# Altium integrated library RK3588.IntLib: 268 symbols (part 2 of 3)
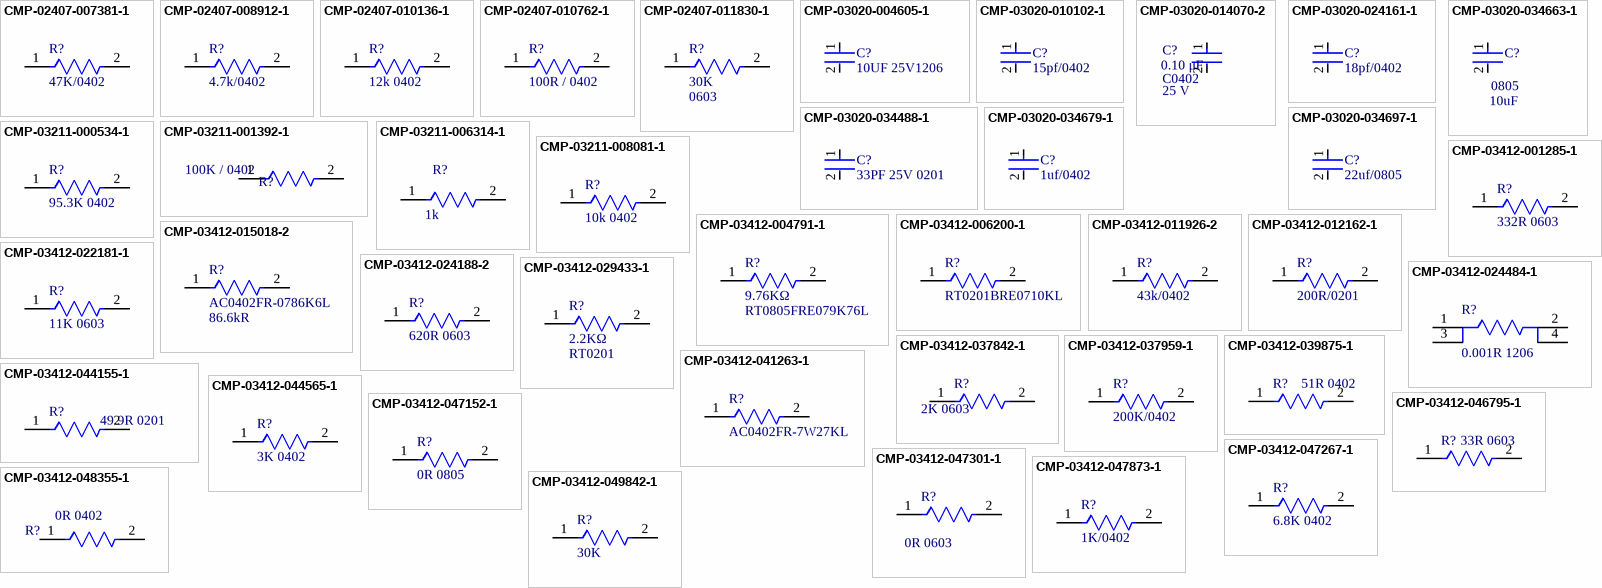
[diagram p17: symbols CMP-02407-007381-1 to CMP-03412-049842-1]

## CMP-02407-008912-1
designator R?, comment 4.7k/0402
RES SMD 1.2K OHM 1% 1/10W 0402
footprint FP-MCS0402-IPC_A
footprint FP-MCS0402-MFG
footprint FP-MCS0402-IPC_C
footprint FP-MCS0402-IPC_B
pins: 1, 2

## CMP-02407-010136-1
designator R?, comment 12k 0402
RES Thick Film, 12kΩ, 1%, 0.063W, 100ppm/°C, 0402; Max Power Dissipation: 63mW; Resistance: 12kR; MP: CRCW040212K0FKEE
footprint FP-CRCW0402-e3-MFG
footprint FP-CRCW0402-e3-IPC_A
footprint FP-CRCW0402-e3-IPC_B
footprint FP-CRCW0402-e3-IPC_C
pins: 1, 2

## CMP-02407-010762-1
designator R?, comment 100R / 0402
RES SMD 1.2K OHM 1% 1/10W 0402; Voltage Rating: 50V; Max Power Dissipation: 100mW; Temperature Coefficient: 50ppm/°C
footprint FP-MCS0402-IPC_C
footprint FP-MCS0402-MFG
footprint FP-MCS0402-IPC_B
footprint FP-MCS0402-IPC_A
pins: 1, 2

## CMP-02407-011830-1
designator R?  value 30K  Case: 0603
30K 0603 / MCT0603MC3002FP500
footprint FP-MCT0603-MFG
footprint FP-MCT0603-IPC_B
footprint FP-MCT0603-IPC_A
footprint FP-MCT0603-IPC_C
pins: 1, 2

## CMP-03020-004605-1
designator C?, comment 10UF 25V1206
CAP CER 10UF 25V X7R 1206 / C1206C106K3RACAUTO; Manufacturer: KEMET; Material: Ceramic; Automotive Grade: Grade 1; Temperature Coefficient: 15%; Tolerance: 10%
footprint FP-C1206C-EH-MFG
footprint FP-C1206C-EH-IPC_C
footprint FP-C1206C-EH-IPC_B
footprint FP-C1206C-EH-IPC_A
pins: 1, 2

## CMP-03020-010102-1
designator C?, comment 15pf/0402
C0402 15 pF X8R 10.00% 50 V; Manufacturer Part Number: C0402C150K5HACAUTO; Manufacturer: Kemet; Tolerance: 0.1; Material: Ceramic; Temperature Coefficient: 15%; Capacitance: 15 pF; Voltage Rating: 50 V; Value: 15 pF
footprint FP-C0402-BB-MFG
footprint FP-C0402-BB-IPC_C
footprint FP-C0402-BB-IPC_B
footprint FP-C0402-BB-IPC_A
pins: 1, 2

## CMP-03020-014070-2
designator C?, comment value 0.10 μF  Package: C0402  Voltage Rating: 25 V  (hidden comment: C0402C104M3PAC7867)
CAP CER 0.1UF 25V X5R 0402; Manufacturer: Kemet; Material: Ceramic; Tolerance: 0.2; Temperature Coefficient: 15%
footprint FP-C0402-BB-MFG
footprint FP-C0402-BB-IPC_C
footprint FP-C0402-BB-IPC_B
footprint FP-C0402-BB-IPC_A
pins: 1, 2

## CMP-03020-024161-1
designator C?, comment 18pf/0402
C0402 18 pF X8R 5.00% 50 V; Manufacturer: Kemet; Manufacturer Part Number: 0402CG180J500NT; Value: 18 pF; Material: Ceramic; Temperature Coefficient: 15%; Tolerance: 0.05; Voltage Rating: 50 V
footprint FP-C0402-BB-MFG
footprint FP-C0402-BB-IPC_C
footprint FP-C0402-BB-IPC_B
footprint FP-C0402-BB-IPC_A
pins: 1, 2

## CMP-03020-034488-1
designator C?, comment 33PF 25V 0201
CAP CER 33PF 25V NP0 0201; Manufacturer Part Number: C0201C330K3GACTU; Manufacturer: KEMET; Standoff Height: 0mm; Tolerance: 0.1; Temperature Characteristic: C0G; Temperature Coefficient: 30ppm/°C; Material: Ceramic
footprint FP-C0201-AB-MFG
footprint FP-C0201-AB-IPC_C
footprint FP-C0201-AB-IPC_B
footprint FP-C0201-AB-IPC_A
pins: 1, 2

## CMP-03020-034663-1
designator C?, comment Capacitance: 10uF  Case/Package: 0805  (hidden comment: C0805C106K3PACTU)
CAP CER 10UF 25V X5R 0805; Dissipation Factor: 10%; Dielectric Material: Ceramic
footprint FP-C0805C106K3PACTU-MFG
footprint FP-C0805C106K3PACTU-IPC_C
footprint FP-C0805C106K3PACTU-IPC_B
footprint FP-C0805C106K3PACTU-IPC_A
pins: 1, 2

## CMP-03020-034679-1
designator C?, comment 1uf/0402
CAP CER 1UF 16V X5R 0402; Dielectric Material: Ceramic; Tolerance: 10%
footprint FP-C0402C-BB-IPC_B
footprint FP-C0402C-BB-MFG
footprint FP-C0402C-BB-IPC_A
footprint FP-C0402C-BB-IPC_C
pins: 1, 2

## CMP-03020-034697-1
designator C?, comment 22uf/0805
CAP CER 22UF 10V X5R 0805; Tolerance: 20%; Dissipation Factor: 10%; Dielectric Material: Ceramic
footprint FP-C0805C226M8PACTU-MFG
footprint FP-C0805C226M8PACTU-IPC_C
footprint FP-C0805C226M8PACTU-IPC_B
footprint FP-C0805C226M8PACTU-IPC_A
pins: 1, 2

## CMP-03211-000534-1
designator R?, comment 95.3K 0402
RP73P 0402 95.3KΩ 0.1W 25ppm/°C 0.10% 50V; Manufacturer Part Number: RP73PF1E95K3BTDF; Manufacturer: TE Connectivity
footprint FP-RP73P-1E-MFG
footprint FP-RP73P-1E-IPC_C
footprint FP-RP73P-1E-IPC_B
footprint FP-RP73P-1E-IPC_A
pins: 1, 2

## CMP-03211-001392-1
designator R?, comment 100K / 0402
SMD Precision Pulse Thick Film Chip Resistor; Manufacturer Part Number: CRGP0402F100K; Manufacturer: TE; Value: 100KΩ; Power Rating: 0.125W; Tolerance: 0.01; Temperature Coefficient: ±100ppm/°C; Voltage Rating: 50V
footprint FP-CRGP0402-IPC_C
footprint FP-CRGP0402-IPC_B
footprint FP-CRGP0402-IPC_A
pins: 1, 2

## CMP-03211-006314-1
designator R?, comment 1k
CRGCQ0402 1KΩ 1% ±100ppm/°C 50V; Manufacturer Part Number: CRGCQ0402F1K0; Manufacturer: TE Connectivity; Power Rating: 0.0625W; Tolerance: 0.01
footprint FP-CRGCQ0402-IPC_C
footprint FP-CRGCQ0402-IPC_B
footprint FP-CRGCQ0402-IPC_A
pins: 1, 2

## CMP-03211-008081-1
designator R?, comment 10k 0402
CRGCQ 0402 10K 5%; Manufacturer: TE Connectivity; Manufacturer Part Number: CRGCQ0402J10K; Power Rating: 0.0625W; Tolerance: 0.05; Voltage Rating: 50V; Temperature Coefficient: ±100ppm/°C; Resistance: 10KΩ; Value: 10KΩ
footprint FP-CRGCQ0402-IPC_C
footprint FP-CRGCQ0402-IPC_B
footprint FP-CRGCQ0402-IPC_A
pins: 1, 2

## CMP-03412-001285-1
designator R?, comment 332R 0603
RES SMD 332 OHM 0.1% 1/10W 0603; Manufacturer Part Number: RT0603BRE07332RL; Manufacturer: Yageo; Voltage Rating: 75V; Tolerance: 0.001; Temperature Coefficient: 50 ppm/°C; Power Rating: 0.1W; Value: 332Ω
footprint FP-RT0603-MFG
footprint FP-RT0603-IPC_C
footprint FP-RT0603-IPC_B
footprint FP-RT0603-IPC_A
pins: 1, 2

## CMP-03412-004791-1
designator R?, comment RT0805FRE079K76L  value 9.76KΩ
RES SMD 9.76K OHM 1% 1/8W 0805; Manufacturer: Yageo; Power Rating: 0.125W; Temperature Coefficient: 50 ppm/°C; Tolerance: 0.0001; Voltage Rating: 150V
footprint FP-RT0805-MFG
footprint FP-RT0805-IPC_C
footprint FP-RT0805-IPC_B
footprint FP-RT0805-IPC_A
pins: 1, 2

## CMP-03412-006200-1
designator R?, comment RT0201BRE0710KL
RT0201 10KΩ 0.05W 50 ppm/°C 0.10%; Manufacturer: Yageo; Voltage Rating: 25V; Tolerance: 0.001
footprint FP-RT0201-MFG
footprint FP-RT0201-IPC_C
footprint FP-RT0201-IPC_B
footprint FP-RT0201-IPC_A
pins: 1, 2

## CMP-03412-011926-2
designator R?, comment 43k/0402
RES 43kΩ ±1% 0.063W 0402; Power Rating: 63mW; Temperature Coefficient: 100ppm/°C; Resistance: 43kR
footprint FP-AC0402-MFG
footprint FP-AC0402-IPC_C
footprint FP-AC0402-IPC_B
footprint FP-AC0402-IPC_A
pins: 1, 2

## CMP-03412-012162-1
designator R?, comment 200R/0201
RES SMD 200 OHM 0.5% 1/20W 0201; Manufacturer Part Number: RT0201DRD07200RL; Manufacturer: Yageo; Tolerance: 0.005; Value: 200Ω; Power Rating: 0.05W; Voltage Rating: 25V; Temperature Coefficient: 25 ppm/°C
footprint FP-RT0201-MFG
footprint FP-RT0201-IPC_C
footprint FP-RT0201-IPC_B
footprint FP-RT0201-IPC_A
pins: 1, 2

## CMP-03412-015018-2
designator R?, comment AC0402FR-0786K6L  Resistance: 86.6kR
RES 86.6kΩ ±1% 0.063W 0402; Voltage Rating: 50V; Power Rating: 62.5mW; Max Power Dissipation: 63mW; Temperature Coefficient: 100ppm/°C
footprint FP-AC0402-IPC_B
footprint FP-AC0402-IPC_C
footprint FP-AC0402-IPC_A
footprint FP-AC0402-MFG
pins: 1, 2

## CMP-03412-022181-1
designator R?, comment 11K 0603
RES SMD 11K OHM 0.1% 1/10W 0603; Manufacturer Part Number: RT0603BRC0711KL; Manufacturer: Yageo; Temperature Coefficient: 15 ppm/°C; Tolerance: 0.001; Value: 11KΩ; Voltage Rating: 75V; Power Rating: 0.1W
footprint FP-RT0603-MFG
footprint FP-RT0603-IPC_C
footprint FP-RT0603-IPC_B
footprint FP-RT0603-IPC_A
pins: 1, 2

## CMP-03412-024188-2
designator R?, comment 620R 0603
RES 620Ω 1.00% 0.1W 0603; Max Power Dissipation: 100mW; Working Voltage: 75V; Voltage Rating: 50V; Tolerance: 1%; Temperature Coefficient: 100ppm/°C
footprint FP-AC0603-IPC_C
footprint FP-AC0603-IPC_A
footprint FP-AC0603-MFG
footprint FP-AC0603-IPC_B
pins: 1, 2

## CMP-03412-024484-1
designator R?, comment 0.001R 1206
METAL CURRECT SENSOR 4 TERMINATI; Manufacturer Part Number: PS0612FKF070R001L; Manufacturer: Yageo; Value: 1mΩ; Temperature Coefficient: 100ppm/°C; Power Rating: 1W; Tolerance: 1%
footprint FP-PS0612-MFG
pins: 1, 2, 3, 4

## CMP-03412-029433-1
designator R?, comment Resistance: 2.2KΩ  Package: RT0201  (hidden comment: RT0201FRE072K2L)
RES SMD 2.2K OHM 1% 1/20W 0201; Manufacturer: Yageo; Value: 2.2KΩ; Power Rating: 0.05W; Temperature Coefficient: 50 ppm/°C; Tolerance: 0.01; Voltage Rating: 25V
footprint FP-RT0201-MFG
footprint FP-RT0201-IPC_C
footprint FP-RT0201-IPC_B
footprint FP-RT0201-IPC_A
pins: 1, 2

## CMP-03412-037842-1
designator R?, comment 2K 0603
RES 2kΩ 1.00% 0.1W 0603; Resistance: 2kR; Tolerance: 1%
footprint FP-AC0603-IPC_B
footprint FP-AC0603-IPC_C
footprint FP-AC0603-MFG
footprint FP-AC0603-IPC_A
pins: 1, 2

## CMP-03412-037959-1
designator R?, comment 200K/0402
RES 200kΩ ±5% 0.063W 0402; Power Rating: 62.5mW; Max Power Dissipation: 63mW; Resistance: 200kR; Temperature Coefficient: 100ppm/°C; Voltage Rating: 50V
footprint FP-AC0402-IPC_B
footprint FP-AC0402-IPC_A
footprint FP-AC0402-IPC_C
footprint FP-AC0402-MFG
pins: 1, 2

## CMP-03412-039875-1
designator R?, comment 51R 0402
Anti-Sulfurated Chip Resistors Automotive Grade 51Ω 5% 100ppm/°C 0402; Max Power Dissipation: 63mW
footprint FP-AF0402-IPC_C
footprint FP-AF0402-IPC_B
footprint FP-AF0402-MFG
footprint FP-AF0402-IPC_A
pins: 1, 2

## CMP-03412-041263-1
designator R?, comment AC0402FR-7W27KL
RES 27kΩ ±1% 0.125W 0402
footprint FP-AC0402-IPC_B
footprint FP-AC0402-IPC_C
footprint FP-AC0402-MFG
footprint FP-AC0402-IPC_A
pins: 1, 2

## CMP-03412-044155-1
designator R?, comment 49.9R 0201
Anti-Sulfurated Chip Resistors Automotive Grade 49.9Ω 1% 200ppm/°C 0201; Max Power Dissipation: 50mW
footprint FP-AF0201-MFG
footprint FP-AF0201-IPC_A
footprint FP-AF0201-IPC_C
footprint FP-AF0201-IPC_B
pins: 1, 2

## CMP-03412-044565-1
designator R?, comment 3K 0402
Thin Film Chip Resistors Automotive Grade 3kΩ 1% 50ppm/°C 0402; MP: AT0402FRE073KL
footprint FP-AT0402-IPC_B
footprint FP-AT0402-MFG
footprint FP-AT0402-IPC_A
footprint FP-AT0402-IPC_C
pins: 1, 2

## CMP-03412-046795-1
designator R?, comment 33R 0603
Anti-Sulfurated Chip Resistors Automotive Grade 33Ω 1% 100ppm/°C 0603; Max Power Dissipation: 100mW; MN: AF0603FR-0733RL
footprint FP-AF0603-IPC_C
footprint FP-AF0603-IPC_A
footprint FP-AF0603-MFG
footprint FP-AF0603-IPC_B
pins: 1, 2

## CMP-03412-047152-1
designator R?, comment 0R 0805
Anti-Sulfurated Chip Resistor Automotive Grade 0Ω Jumper 0.125W 0805; Max Power Dissipation: 125mW
footprint FP-AF0805-IPC_B
footprint FP-AF0805-IPC_C
footprint FP-AF0805-MFG
footprint FP-AF0805-IPC_A
pins: 1, 2

## CMP-03412-047267-1
designator R?, comment 6.8K 0402
RES 6.8kΩ ±5% 0.125W 0402; MP: AC0402JR-7W6K8L
footprint FP-AC0402-MFG
footprint FP-AC0402-IPC_B
footprint FP-AC0402-IPC_C
footprint FP-AC0402-IPC_A
pins: 1, 2

## CMP-03412-047301-1
designator R?, comment 0R 0603
RES 0Ω 5.00% 0.1W 0603; Resistance: 0mR; Tolerance: 5%
footprint FP-AC0603-IPC_C
footprint FP-AC0603-IPC_B
footprint FP-AC0603-MFG
footprint FP-AC0603-IPC_A
pins: 1, 2

## CMP-03412-047873-1
designator R?, comment 1K/0402
RES 1kΩ ±1% 0.063W 0402
footprint FP-AC0402-IPC_C
footprint FP-AC0402-IPC_A
footprint FP-AC0402-IPC_B
footprint FP-AC0402-MFG
pins: 1, 2

## CMP-03412-048355-1
designator R?, comment 0R 0402
Anti-Sulfurated Chip Resistors Automotive Grade 0Ω 0402; Tolerance: 5%; MP: AF0402JR-070RL
footprint FP-AF0402-MFG
footprint FP-AF0402-IPC_B
footprint FP-AF0402-IPC_A
footprint FP-AF0402-IPC_C
pins: 1, 2

## CMP-03412-049842-1
designator R?, comment 30K
Thin Film Chip Resistors Automotive Grade 30kΩ 1% 50ppm/°C 0603
footprint FP-AT0603-IPC_B
footprint FP-AT0603-MFG
footprint FP-AT0603-IPC_C
footprint FP-AT0603-IPC_A
pins: 1, 2

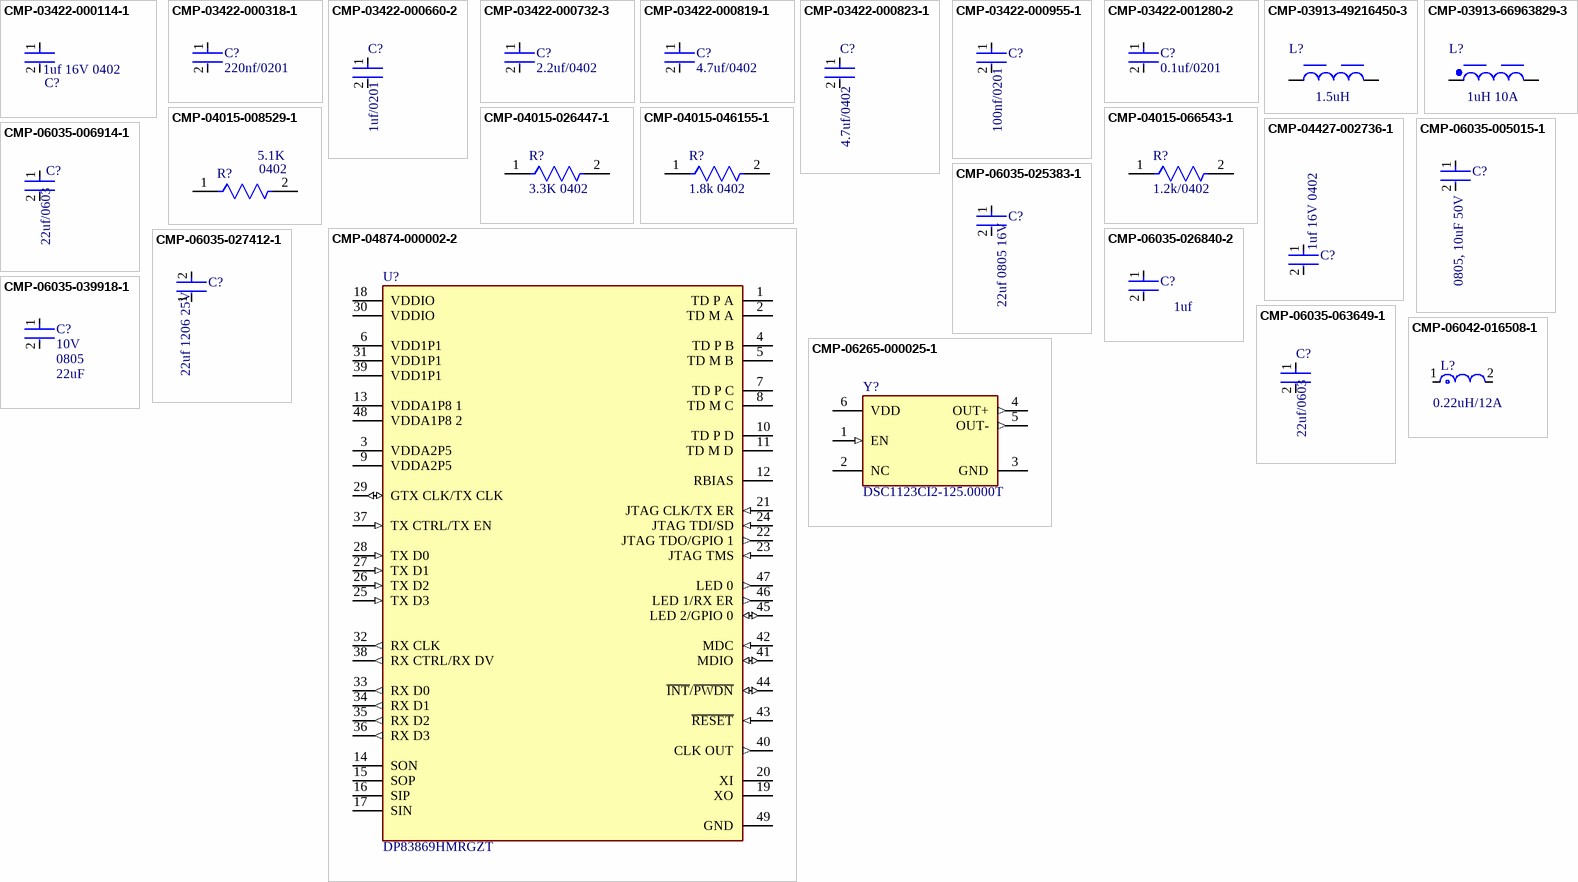
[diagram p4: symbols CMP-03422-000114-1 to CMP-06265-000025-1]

## CMP-03422-000114-1
designator C?, comment 1uf 16V 0402
CAP CER 1UF 25V X5R 0402; Manufacturer Part Number: CC0402KRX5R8BB105; Manufacturer: YAGEO; Automotive Grade: NA; Tolerance: 0.1; Material: Ceramic; Temperature Coefficient: 30ppm/°C
footprint FP-CC0402-MFG
footprint FP-CC0402-IPC_C
footprint FP-CC0402-IPC_B
footprint FP-CC0402-IPC_A
pins: 1, 2

## CMP-03422-000318-1
designator C?, comment 220nf/0201
CC0201 220 nF X5R 10.00% 10 V; Manufacturer: Yageo; Material: Ceramic; Capacitance: 220 nF; MN: CC0201KRX5R6BB224; Voltage Rating: 10 V; Temperature Coefficient: 15%; Value: 220 nF; Tolerance: 0.1
footprint FP-CC0201-BA-MFG
footprint FP-CC0201-BA-IPC_C
footprint FP-CC0201-BA-IPC_B
footprint FP-CC0201-BA-IPC_A
pins: 1, 2

## CMP-03422-000660-2
designator C?, comment 1uf/0201
1uF 6.3V X5R ±20% 0201 Multilayer Ceramic Capacitors MLCC - SMD/SMT ROHS; Manufacturer: Yageo; Manufacturer Part Number: CC0201MRX5R5BB105; Tolerance: 0.2; Temperature Coefficient: 15%; MN: CL03A105MQ3CSNH
footprint FP-CC0201-BA-MFG
footprint FP-CC0201-BA-IPC_C
footprint FP-CC0201-BA-IPC_B
footprint FP-CC0201-BA-IPC_A
signal-integrity model Model Name (Model Description)
pins: 1, 2

## CMP-03422-000732-3
designator C?, comment 2.2uf/0402
CAP CER 2.2UF 16V X5R 0402; Tolerance: 10%
footprint FP-CC0402-CC-MFG
footprint FP-CC0402-CC-IPC_C
footprint FP-CC0402-CC-IPC_B
footprint FP-CC0402-CC-IPC_A
pins: 1, 2

## CMP-03422-000819-1
designator C?, comment 4.7uf/0402
CAP CER 4.7UF 16V X5R 0402; Manufacturer Part Number: CC0402MRX5R7BB475; Manufacturer: YAGEO; Tolerance: 0.2; Automotive Grade: NA; Material: Ceramic; Temperature Coefficient: 30ppm/°C
footprint FP-CC0402-MFG
footprint FP-CC0402-IPC_C
footprint FP-CC0402-IPC_B
footprint FP-CC0402-IPC_A
pins: 1, 2

## CMP-03422-000823-1
designator C?, comment 4.7uf/0402
10V 4.7uF X5R ±10% 0402 Multilayer Ceramic Capacitors MLCC - SMD/SMT ROHS; Manufacturer Part Number: CC0402KRX5R6BB475; Manufacturer: YAGEO; Automotive Grade: NA; Temperature Coefficient: 30ppm/°C; Tolerance: 0.1
footprint FP-CC0402-MFG
footprint FP-CC0402-IPC_C
footprint FP-CC0402-IPC_B
footprint FP-CC0402-IPC_A
pins: 1, 2

## CMP-03422-000955-1
designator C?, comment 100nf/0201
CC0201 100 nF X5R 20.00% 10 V; Manufacturer: Yageo; Manufacturer Part Number: CC0201MRX5R6BB104; Tolerance: 0.2; Temperature Coefficient: 15%; Capacitance: 100 nF; Voltage Rating: 10 V; Value: 100 nF; Material: Ceramic
footprint FP-CC0201-BA-MFG
footprint FP-CC0201-BA-IPC_C
footprint FP-CC0201-BA-IPC_B
footprint FP-CC0201-BA-IPC_A
pins: 1, 2

## CMP-03422-001280-2
designator C?, comment 0.1uf/0201
CAP CER 0.1UF 25V X5R 0201
footprint FP-CC0201-BB-MFG
footprint FP-CC0201-BB-IPC_C
footprint FP-CC0201-BB-IPC_B
footprint FP-CC0201-BB-IPC_A
pins: 1, 2

## CMP-03913-49216450-3
designator L?, comment 1.5uH
Fixed Ind 1.5UH 3.7A 39 Mohm SMD; Shielding: Shielded; Saturation Current: 4.5A; Inductance Tolerance: 20%; Core Material: Composite, Ferrite, Metal; Test Frequency: 100kHz; Self Resonant Frequency: 51MHz; DC Resistance (DCR): 33mΩ; Inductance: 1.5µH
footprint WE-MAPI_3020
pins: 1, 2

## CMP-03913-66963829-3
designator L?, comment 1uH 10A
Inductor Power Shielded Wirewound 1uH 20% 100KHz Metal 10.1A 0.015Ohm DCR T/R Automotive AEC-Q200; Core Material: Composite, Metal; Current Rating: 7.2A; Self Resonant Frequency: 55MHz; Inductance: 1µH; Saturation Current: 9A; DC Resistance (DCR): 12mΩ
footprint WE-MAPI_4020
pins: 1, 2

## CMP-04015-008529-1
designator R?, comment value 5.1K  Case/Package: 0402  (hidden comment: 5.1K 0402)
5.1kΩ ±1% 0.063W, 1/16W Chip Resistor 0402 (1005 Metric) Moisture Resistant Thin Film; MN: RN73R1ETTP5101F25
footprint FP-RN73R1E-IPC_C
footprint FP-RN73R1E-MFG
footprint FP-RN73R1E-IPC_B
footprint FP-RN73R1E-IPC_A
pins: 1, 2

## CMP-04015-026447-1
designator R?, comment 3.3K 0402
3.3kΩ ±1% 0.063W, 1/16W Chip Resistor 0402 (1005 Metric) Moisture Resistant Thin Film
footprint FP-RN73R1E-IPC_B
footprint FP-RN73R1E-IPC_A
footprint FP-RN73R1E-IPC_C
footprint FP-RN73R1E-MFG
pins: 1, 2

## CMP-04015-046155-1
designator R?, comment 1.8k 0402
1.8kΩ ±0.1% 0.063W, 1/16W Chip Resistor 0402 (1005 Metric) Moisture Resistant Thin Film; MN: RN73R1ETTP1801B25
footprint FP-RN73R1E-IPC_C
footprint FP-RN73R1E-IPC_A
footprint FP-RN73R1E-IPC_B
footprint FP-RN73R1E-MFG
pins: 1, 2

## CMP-04015-066543-1
designator R?, comment 1.2k/0402
1.2kΩ ±1% 0.063W, 1/16W Chip Resistor 0402 (1005 Metric) Moisture Resistant Thin Film
footprint FP-RN73R1E-IPC_B
footprint FP-RN73R1E-MFG
footprint FP-RN73R1E-IPC_A
footprint FP-RN73R1E-IPC_C
pins: 1, 2

## CMP-04427-002736-1
designator C?, comment 1uf 16V 0402
General Purpose Ceramic Capacitor, 0402, 1uF, 20%, X5R, 15%, 16V
footprint FP-0402-L_1_0_1-W_0_5_0_1-MFG
footprint FP-0402-L_1_0_1-W_0_5_0_1-IPC_C
footprint FP-0402-L_1_0_1-W_0_5_0_1-IPC_B
footprint FP-0402-L_1_0_1-W_0_5_0_1-IPC_A
pins: 1, 2

## CMP-04874-000002-2
designator U?, comment DP83869HMRGZT
IC TRANSCEIVER 1/1 48FN
footprint FP-RGZ0048B-IPC_A
footprint FP-RGZ0048B-IPC_C
footprint FP-RGZ0048B-IPC_B
footprint FP-RGZ0048B-MFG
pins: 1 TD P A, 2 TD M A, 3 VDDA2P5 (power), 4 TD P B, 5 TD M B, 6 VDD1P1 (power), 7 TD P C, 8 TD M C, 9 VDDA2P5 (power), 10 TD P D, 11 TD M D, 12 RBIAS, 13 VDDA1P8 1 (power), 14 SON, 15 SOP, 16 SIP, 17 SIN, 18 VDDIO (power), 19 XO, 20 XI, 21 JTAG CLK/TX ER (in), 22 JTAG TDO/GPIO 1 (out), 23 JTAG TMS (in), 24 JTAG TDI/SD (in), 25 TX D3 (in), 26 TX D2 (in), 27 TX D1 (in), 28 TX D0 (in), 29 GTX CLK/TX CLK (io), 30 VDDIO (power), 31 VDD1P1 (power), 32 RX CLK (out), 33 RX D0 (out), 34 RX D1 (out), 35 RX D2 (out), 36 RX D3 (out), 37 TX CTRL/TX EN (in), 38 RX CTRL/RX DV (out), 39 VDD1P1 (power), 40 CLK OUT (out), 41 MDIO (io), 42 MDC (in), 43 ~{RESET} (in), 44 ~{INT}/~{PWDN} (io), 45 LED 2/GPIO 0 (io), 46 LED 1/RX ER (out), 47 LED 0 (out), 48 VDDA1P8 2 (power), 49 GND (power)

## CMP-06035-005015-1
designator C?, comment 0805, 10uF 50V
Chip Multilayer Ceramic Capacitors for General Purpose, 0805, 10uF, X5R, 15%, 10%, 50V / GRM21BR61H106KE43K
footprint FP-GRM21B-0_2-e0_2_0_7-IPC_C
footprint FP-GRM21B-0_2-e0_2_0_7-IPC_A
footprint FP-GRM21B-0_2-e0_2_0_7-IPC_B
footprint FP-GRM21B-0_2-e0_2_0_7-MFG
pins: 1, 2

## CMP-06035-006914-1
designator C?, comment 22uf/0603
Chip Multilayer Ceramic Capacitors for General Purpose, 0603, 22uF, X5R, 15%, 20%, 6.3V
footprint FP-GRM186-0_2-MFG
footprint FP-GRM186-0_2-IPC_C
footprint FP-GRM186-0_2-IPC_A
footprint FP-GRM186-0_2-IPC_B
pins: 1, 2

## CMP-06035-025383-1
designator C?, comment 22uf 0805 16V
Chip Multilayer Ceramic Capacitors for General Purpose, 0805, 22uF, X5R, 15%, 20%, 16V
footprint FP-GRM21B-0_2-e0_2_0_7-IPC_C
footprint FP-GRM21B-0_2-e0_2_0_7-IPC_A
footprint FP-GRM21B-0_2-e0_2_0_7-IPC_B
footprint FP-GRM21B-0_2-e0_2_0_7-MFG
pins: 1, 2

## CMP-06035-026840-2
designator C?, comment value 1uf  (hidden comment: GRM155R61H105KE05D)
CERAMIC CAP, MLCC 1UF 50VDC X5R
footprint FP-GRM155-0_1-MFG
footprint FP-GRM155-0_1-IPC_C
footprint FP-GRM155-0_1-IPC_B
footprint FP-GRM155-0_1-IPC_A
pins: 1, 2

## CMP-06035-027412-1
designator C?, comment 22uf 1206 25V
Chip Multilayer Ceramic Capacitors for General Purpose, 1206, 22uF, X6S, 22%, 20%, 25V / GRM31CC81E226ME11K
footprint FP-GRM31C-0_3-e0_3_0_8-IPC_A
footprint FP-GRM31C-0_3-e0_3_0_8-IPC_C
footprint FP-GRM31C-0_3-e0_3_0_8-MFG
footprint FP-GRM31C-0_3-e0_3_0_8-IPC_B
pins: 1, 2

## CMP-06035-039918-1
designator C?, comment Voltage: 10V  Case Code (Imperial): 0805  Capacitance: 22uF  (hidden comment: GRM21BR61A226ME44L)
Chip Multilayer Ceramic Capacitors for General Purpose, 0805, 22uF, X5R, 15%, 20%, 10V / GRM21BR61A226ME44L; Dissipation Factor: 0.035%
footprint FP-GRM21B-0_2-e0_2_0_7-IPC_C
footprint FP-GRM21B-0_2-e0_2_0_7-IPC_B
footprint FP-GRM21B-0_2-e0_2_0_7-MFG
footprint FP-GRM21B-0_2-e0_2_0_7-IPC_A
pins: 1, 2

## CMP-06035-063649-1
designator C?, comment 22uf/0603
10V 22uF X5R ±20% 0603 Multilayer Ceramic Capacitors MLCC - SMD/SMT ROHS; MN: CL10A226MP8NUNE
footprint FP-GRM188-0_2-MFG
footprint FP-GRM188-0_2-IPC_B
footprint FP-GRM188-0_2-IPC_C
footprint FP-GRM188-0_2-IPC_A
pins: 1, 2

## CMP-06042-016508-1
designator L?, comment 0.22uH/12A
FIXED IND
footprint FP-FDSD0415-MFG
pins: 1, 2

## CMP-06265-000025-1
designator Y?, comment DSC1123CI2-125.0000T
MEMS OSC XO 125.0000MHZ LVDS SMD; Frequency Stability: 25ppm; Max Supply Current: 32mA; Min Supply Voltage: 2.25V; Max Supply Voltage: 3.6V; Frequency: 125MHz; Max Duty Cycle: 52%; Load Capacitance: 2pF
footprint FP-C04-1007-MFG
pins: 1 EN (in), 2 NC, 3 GND (power), 4 OUT+ (out), 5 OUT- (out), 6 VDD (power)

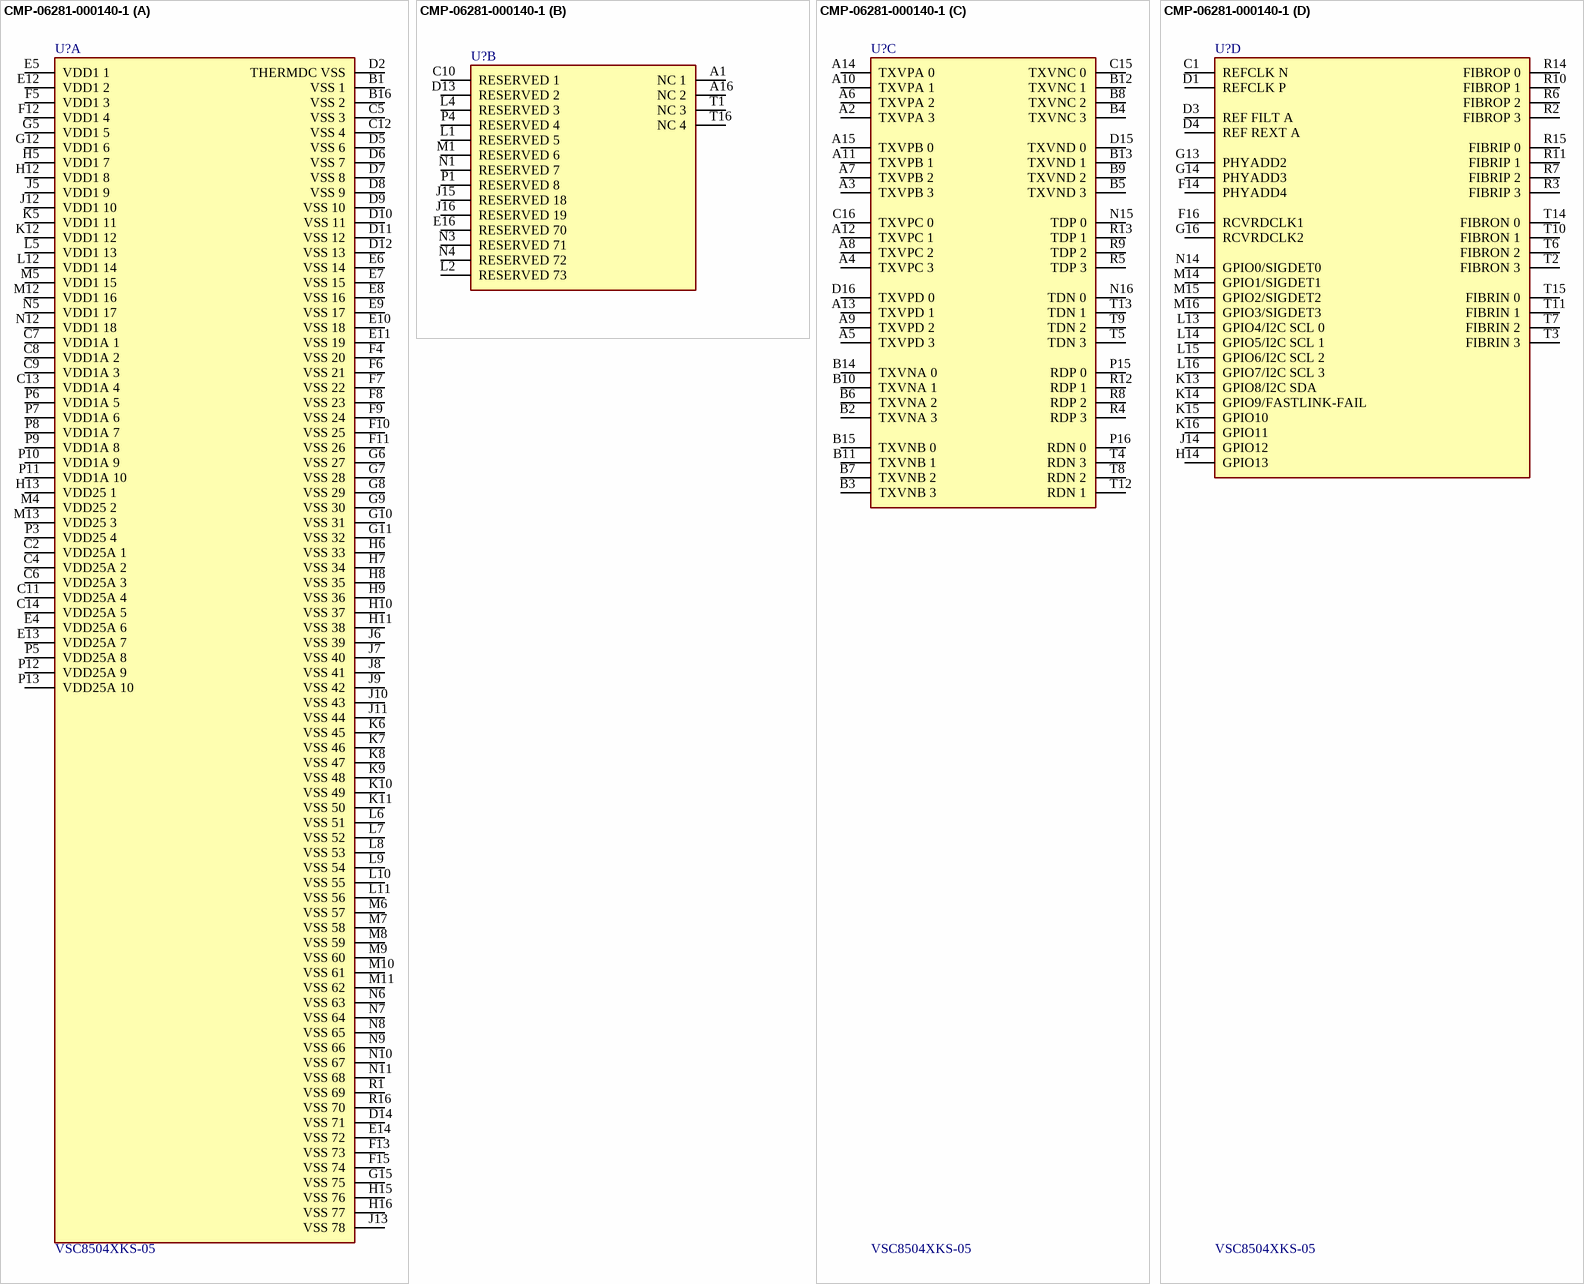
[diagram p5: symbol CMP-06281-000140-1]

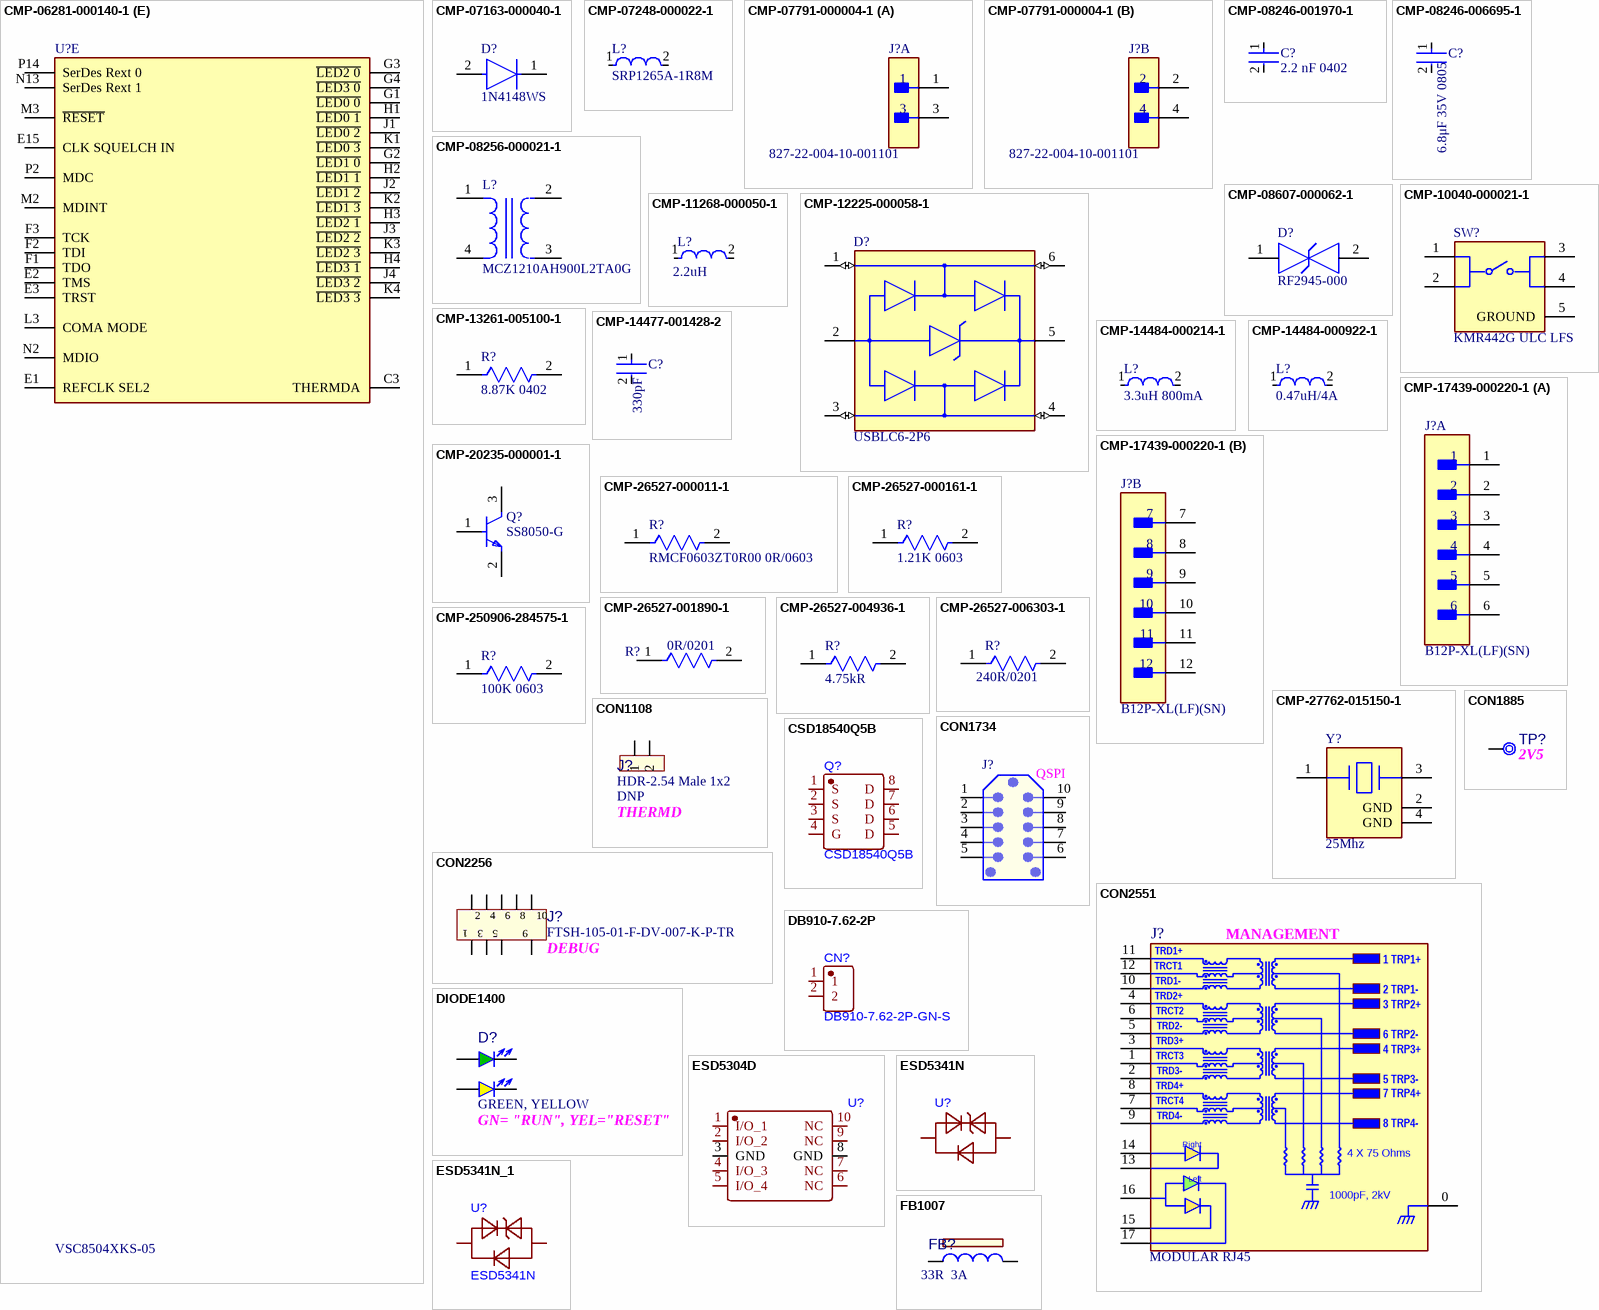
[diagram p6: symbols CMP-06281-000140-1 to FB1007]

## CMP-06281-000140-1
designator U?, comment VSC8504XKS-05
IC TELECOM INTERFACE 256BGA; Number of Circuits: 1
footprint FP-VSC8504XKS-05-IPC_C
footprint FP-VSC8504XKS-05-IPC_B
footprint FP-VSC8504XKS-05-IPC_A
part A pins: B1 VSS 1, B16 VSS 2, C2 VDD25A 1, C4 VDD25A 2, C5 VSS 3, C6 VDD25A 3, C7 VDD1A 1, C8 VDD1A 2, C9 VDD1A 3, C11 VDD25A 4, C12 VSS 4, C13 VDD1A 4, C14 VDD25A 5, D2 THERMDC VSS, D5 VSS 6, D6 VSS 7, D7 VSS 8, D8 VSS 9, D9 VSS 10, D10 VSS 11, D11 VSS 12, D12 VSS 13, D14 VSS 71, E4 VDD25A 6, E5 VDD1 1, E6 VSS 14, E7 VSS 15, E8 VSS 16, E9 VSS 17, E10 VSS 18, E11 VSS 19, E12 VDD1 2, E13 VDD25A 7, E14 VSS 72, F4 VSS 20, F5 VDD1 3, F6 VSS 21, F7 VSS 22, F8 VSS 23, F9 VSS 24, F10 VSS 25, F11 VSS 26, F12 VDD1 4, F13 VSS 73, F15 VSS 74, G5 VDD1 5, G6 VSS 27, G7 VSS 28, G8 VSS 29, G9 VSS 30, G10 VSS 31, G11 VSS 32, G12 VDD1 6, G15 VSS 75, H5 VDD1 7, H6 VSS 33, H7 VSS 34, H8 VSS 35, H9 VSS 36, H10 VSS 37, H11 VSS 38, H12 VDD1 8, H13 VDD25 1, H15 VSS 76, H16 VSS 77, J5 VDD1 9, J6 VSS 39, J7 VSS 40, J8 VSS 41, J9 VSS 42, J10 VSS 43, J11 VSS 44, J12 VDD1 10, J13 VSS 78, K5 VDD1 11, K6 VSS 45, K7 VSS 46, K8 VSS 47, K9 VSS 48, K10 VSS 49, K11 VSS 50, K12 VDD1 12, L5 VDD1 13, L6 VSS 51, L7 VSS 52, L8 VSS 53, L9 VSS 54, L10 VSS 55, L11 VSS 56, L12 VDD1 14, M4 VDD25 2, M5 VDD1 15, M6 VSS 57, M7 VSS 58, M8 VSS 59, M9 VSS 60, M10 VSS 61, M11 VSS 62, M12 VDD1 16, M13 VDD25 3, N5 VDD1 17, N6 VSS 63, N7 VSS 64, N8 VSS 65, N9 VSS 66, N10 VSS 67, N11 VSS 68, N12 VDD1 18, P3 VDD25 4, P5 VDD25A 8, P6 VDD1A 5, P7 VDD1A 6, P8 VDD1A 7, P9 VDD1A 8, P10 VDD1A 9, P11 VDD1A 10, P12 VDD25A 9, P13 VDD25A 10, R1 VSS 69, R16 VSS 70
part B pins: A1 NC 1, A16 NC 2, C10 RESERVED 1, D13 RESERVED 2, E16 RESERVED 70, J15 RESERVED 18, J16 RESERVED 19, L1 RESERVED 5, L2 RESERVED 73, L4 RESERVED 3, M1 RESERVED 6, N1 RESERVED 7, N3 RESERVED 71, N4 RESERVED 72, P1 RESERVED 8, P4 RESERVED 4, T1 NC 3, T16 NC 4
part C pins: A2 TXVPA 3, A3 TXVPB 3, A4 TXVPC 3, A5 TXVPD 3, A6 TXVPA 2, A7 TXVPB 2, A8 TXVPC 2, A9 TXVPD 2, A10 TXVPA 1, A11 TXVPB 1, A12 TXVPC 1, A13 TXVPD 1, A14 TXVPA 0, A15 TXVPB 0, B2 TXVNA 3, B3 TXVNB 3, B4 TXVNC 3, B5 TXVND 3, B6 TXVNA 2, B7 TXVNB 2, B8 TXVNC 2, B9 TXVND 2, B10 TXVNA 1, B11 TXVNB 1, B12 TXVNC 1, B13 TXVND 1, B14 TXVNA 0, B15 TXVNB 0, C15 TXVNC 0, C16 TXVPC 0, D15 TXVND 0, D16 TXVPD 0, N15 TDP 0, N16 TDN 0, P15 RDP 0, P16 RDN 0, R4 RDP 3, R5 TDP 3, R8 RDP 2, R9 TDP 2, R12 RDP 1, R13 TDP 1, T4 RDN 3, T5 TDN 3, T8 RDN 2, T9 TDN 2, T12 RDN 1, T13 TDN 1
part D pins: C1 REFCLK N, D1 REFCLK P, D3 REF FILT A, D4 REF REXT A, F14 PHYADD4, F16 RCVRDCLK1, G13 PHYADD2, G14 PHYADD3, G16 RCVRDCLK2, H14 GPIO13, J14 GPIO12, K13 GPIO8/I2C SDA, K14 GPIO9/FASTLINK-FAIL, K15 GPIO10, K16 GPIO11, L13 GPIO4/I2C SCL 0, L14 GPIO5/I2C SCL 1, L15 GPIO6/I2C SCL 2, L16 GPIO7/I2C SCL 3, M14 GPIO1/SIGDET1, M15 GPIO2/SIGDET2, M16 GPIO3/SIGDET3, N14 GPIO0/SIGDET0, R2 FIBROP 3, R3 FIBRIP 3, R6 FIBROP 2, R7 FIBRIP 2, R10 FIBROP 1, R11 FIBRIP 1, R14 FIBROP 0, R15 FIBRIP 0, T2 FIBRON 3, T3 FIBRIN 3, T6 FIBRON 2, T7 FIBRIN 2, T10 FIBRON 1, T11 FIBRIN 1, T14 FIBRON 0, T15 FIBRIN 0
part E pins: C3 THERMDA, E1 REFCLK SEL2, E2 TMS, E3 TRST, E15 CLK SQUELCH IN, F1 TDO, F2 TDI, F3 TCK, G1 ~{LED0 0}, G2 ~{LED1 0}, G3 ~{LED2 0}, G4 ~{LED3 0}, H1 ~{LED0 1}, H2 ~{LED1 1}, H3 ~{LED2 1}, H4 ~{LED3 1}, J1 ~{LED0 2}, J2 ~{LED1 2}, J3 ~{LED2 2}, J4 ~{LED3 2}, K1 ~{LED0 3}, K2 ~{LED1 3}, K3 ~{LED2 3}, K4 ~{LED3 3}, L3 COMA MODE, M2 MDINT, M3 ~{RESET}, N2 MDIO, N13 SerDes Rext 1, P2 MDC, P14 SerDes Rext 0

## CMP-07163-000040-1
designator D?, comment 1N4148WS
DIODE GEN PURP 75V 150MA SOD323F; Forward Voltage: 1V; Power Dissipation: 200mW; Element Configuration: Single; Max Forward Surge Current (Ifsm): 2A; Peak Reverse Current: 5uA; Recovery Time: 4ns
footprint FP-477AB-IPC_C
footprint FP-477AB-IPC_B
footprint FP-477AB-IPC_A
pins: 1 C, 2 A

## CMP-07248-000022-1
designator L?, comment SRP1265A-1R8M
FIXED IND 1.8UH 24A 4.0 MOHM SMD; Manufacturer: Bourns; Self Resonant Frequency: 30MHz; Automotive Grade: Grade 0; Series Resistance: 4mΩ; Tolerance: 20%; Shielding: true; Test Frequency: 100kHz; Core Material: Carbonyl Powder; Saturation Current: 40A; Q Factor: 20
footprint FP-SRP1265A-MFG
pins: 1, 2

## CMP-07791-000004-1
designator J?, comment 827-22-004-10-001101
CONN SPRING PISTON 4POS PCB; Manufacturer: Mill-Max; Pitch: 2.54mm; Conn Gender: Male; Conn Orientation: Vertical; Number Of Contacts: 4
footprint FP-827-22-004-10-001101-MFG
part A pins: 1, 3
part B pins: 2, 4

## CMP-08246-001970-1
designator C?, comment 2.2 nF 0402
Cap Ceramic 2.2nF 50V X7R 10% Pad SMD 0402 +125°C Automotive T/R
footprint FP-CGA2B-IPC_B
footprint FP-CGA2B-IPC_C
footprint FP-CGA2B-MFG
footprint FP-CGA2B-IPC_A
pins: 1, 2

## CMP-08246-006695-1
designator C?, comment 6.8μF 35V 0805
Multilayer Ceramic Capacitors 6.8μF ±10% 35V X5R SMD 0805 / C2012X5R1V685K125AC; Capacitance: 6.8uF
footprint FP-C2012-125-0_2-IPC_B
footprint FP-C2012-125-0_2-IPC_C
footprint FP-C2012-125-0_2-IPC_A
footprint FP-C2012-125-0_2-MFG
pins: 1, 2

## CMP-08256-000021-1
designator L?, comment MCZ1210AH900L2TA0G
CMC 100MA 2LN 90 OHM SMD
footprint FP-MCZ1210AH-MFG
pins: 1, 2, 3, 4

## CMP-08607-000062-1
designator D?, comment RF2945-000
TVS DIODE 7V 10V 0402; Manufacturer: Littelfuse; Value: 0.1pF; Breakdown Voltage: 9.8V; Number Of Channels: 1; Peak Pulse Current: 2A; Direction: Bidirectional; Automotive Grade: Grade 1; Standoff Height: 0mm
footprint FP-SESD0402-MFG
pins: 1, 2

## CMP-10040-000021-1
designator SW?, comment KMR442G ULC LFS
SWITCH TACTILE SPST-NO 0.05A 32V; Actuator Type: Standard; Actuator Length: 1.1mm; Max Current Rating: 50mA; Illumination Type: Non-Illuminated; Operating Force: 4N; Switch Travel: 0.35mm; Throw Configuration: SPST; Switch Function: Off-Mom; Mechanical Life: 200000Cycles; Power Rating: 1W
footprint FP-KMR442G_ULC_LFS-MFG
pins: 1, 2, 3, 4, 5 GROUND (power)

## CMP-11268-000050-1
designator L?, comment Inductance: 2.2uH  (hidden comment: XAL5030-222MEB)
Fixed Inductors 2.2uH 20% 9.7A 14.5mOhms; DC Resistance (DCR): 14.5mR; Shielding: Shielded; Max DC Current: 9.2A; Test Frequency: 100kHz; Self Resonant Frequency: 38MHz; Core Material: Composite
footprint FP-XAL5030-222MEB-MFG
pins: 1, 2

## CMP-12225-000058-1
designator D?, comment USBLC6-2P6
TVS DIODE 5.25V 17V SOT666; Min Breakdown Voltage: 6V; Power Line Protection: Yes; Element Configuration: Dual; Test Current: 1mA; Working Voltage: 5V; Number of Channels: 2; Max Reverse Leakage Current: 150nA; Direction: Unidirectional; Peak Pulse Current: 5A; Number of Elements: 1; Capacitance: 3.5pF
footprint FP-SOT-666-MFG
pins: 1 I/O1 (io), 2 GND (power), 3 I/O2 (io), 4 I/O2 (io), 5 VBUS (power), 6 I/O1 (io)

## CMP-13261-005100-1
designator R?, comment 8.87K 0402
Res Thick Film 0402 8.87kΩ 1% 0.063W ±100ppm/°C Molded SMD T/R; Voltage Rating (DC): 50V; Max Power Dissipation: 63mW; Resistance: 8.87kR
footprint FP-RC1005-IPC_A
footprint FP-RC1005-MFG
footprint FP-RC1005-IPC_B
footprint FP-RC1005-IPC_C
pins: 1, 2

## CMP-14477-001428-2
designator C?, comment Capacitance: 330pF  (hidden comment: UMK105CG331JV-F)
Voltage Rating: 50V; Tolerance: 5%; Dielectric: C0G
footprint FP-0402-L_1_0_0_05-W_0_5-MFG
footprint FP-0402-L_1_0_0_05-W_0_5-IPC_A
footprint FP-0402-L_1_0_0_05-W_0_5-IPC_B
footprint FP-0402-L_1_0_0_05-W_0_5-IPC_C
pins: 1, 2

## CMP-14484-000214-1
designator L?, comment 3.3uH 800mA
SMD Inductors 3.3uH ±20% 0.8A 0.26Ω 0806; DC Resistance (DCR): 260mR; Saturation Current: 400mA; Test Frequency: 7.96MHz; Shielding: Unshielded; Core Material: Ferrite; Self Resonant Frequency: 55MHz
footprint FP-CB2016-MFG
footprint FP-CB2016-IPC_B
footprint FP-CB2016-IPC_A
footprint FP-CB2016-IPC_C
pins: 1, 2

## CMP-14484-000922-1
designator L?, comment 0.47uH/4A
Inductor Power Shielded Wirewound 0.47uH 30% 100KHz Ferrite 5A 13mΩ DCR Automotive T/R; DC Resistance (DCR): 13mR; Saturation Current: 9A; Inductance: 470nH; Self Resonant Frequency: 185MHz
footprint FP-NRS5030-H_3_1-MFG
pins: 1, 2

## CMP-17439-000220-1
designator J?, comment B12P-XL(LF)(SN)
XL Connector Wire to Board 12PIN; Number of Contacts: 12; Current Rating: 10A; Pitch: 5mm; Voltage Rating: 150V
footprint FP-B12P-XL_LF_SN-MFG
part A pins: 1, 2, 3, 4, 5, 6
part B pins: 7, 8, 9, 10, 11, 12

## CMP-20235-000001-1
designator Q?, comment SS8050-G
NPN TRANSISTOR 1.5A 40V SOT-23 R; Transition Frequency: 100MHz; Max Breakdown Voltage: 25V; Collector Emitter Voltage (VCEO): 400mV; Max Power Dissipation: 300mW
footprint FP-SS8050-G-MFG
footprint FP-SS8050-G-IPC_C
footprint FP-SS8050-G-IPC_B
footprint FP-SS8050-G-IPC_A
pins: 1 B, 2 E, 3 C

## CMP-26527-000011-1
designator R?, comment RMCF0603ZT0R00 0R/0603
RES 0 OHM JUMPER 1/10W 0603; Manufacturer: Stackpole; Power Rating: 0.1W; Voltage Rating: 75V; Resistance: 0mΩ; Automotive Grade: Grade 0; Value: 0mΩ
footprint FP-RMCF0603-MFG
footprint FP-RMCF0603-IPC_C
footprint FP-RMCF0603-IPC_B
footprint FP-RMCF0603-IPC_A
pins: 1, 2

## CMP-26527-000161-1
designator R?, comment 1.21K 0603
1.21kΩ ±1% 0.1W 0603 Thick Film Chip Resistor AEC-Q200 compliant / RMCF0603FG1K21; Max Power Dissipation: 100mW; Temperature Coefficient: 100ppm/°C; Resistance: 1.21kR
footprint FP-RMCF0603-IPC_B
footprint FP-RMCF0603-MFG
footprint FP-RMCF0603-IPC_A
footprint FP-RMCF0603-IPC_C
pins: 1, 2

## CMP-26527-001890-1
designator R?, comment 0R/0201
-55℃~+155℃ 0Ω 25V 50mW Thick Film Resistor 0201 Chip Resistor - Surface Mount ROHS; Resistance: 0R; MN: RMCF0201ZT0R00
footprint FP-RMCF0201-IPC_C
footprint FP-RMCF0201-MFG
footprint FP-RMCF0201-IPC_B
footprint FP-RMCF0201-IPC_A
pins: 1, 2

## CMP-26527-004936-1
designator R?, comment Resistance: 4.75kR  (hidden comment: RNCP0805FTD4K75)
4.75kΩ ±1% 0.25W 0805 High Power Anti-Sulfur Thin Film Chip Resistor; Temperature Coefficient: 100ppm/°C; Max Power Dissipation: 250mW
footprint FP-RNCP0805-IPC_A
footprint FP-RNCP0805-MFG
footprint FP-RNCP0805-IPC_B
footprint FP-RNCP0805-IPC_C
pins: 1, 2

## CMP-26527-006303-1
designator R?, comment 240R/0201
240Ω ±1% 0.05W 0201 Thick Film Chip Resistor AEC-Q200 compliant; Temperature Coefficient: 200ppm/°C; Resistance: 240R; Max Power Dissipation: 50mW
footprint FP-RMCF0201-IPC_C
footprint FP-RMCF0201-IPC_B
footprint FP-RMCF0201-MFG
footprint FP-RMCF0201-IPC_A
pins: 1, 2

## CMP-27762-015150-1
designator Y?, comment 25Mhz
Crystal 25MHz ±20ppm (Tol) ±100ppm (Stability) 12pF FUND 50Ω Automotive 4-Pin Ultra Mini-CSMD T/R; ESR (Equivalent Series Resistance): 50R
footprint FP-ABM8AIG-MFG
pins: 1, 2 GND (power), 3, 4 GND (power)

## CMP-250906-284575-1
designator R?, comment 100K 0603
RES Thin Film,  100kΩ, 0.1%, 0.1W, 25ppm/°C, 0603
footprint FP-TFCR0603-IPC_B
footprint FP-TFCR0603-IPC_C
footprint FP-TFCR0603-IPC_A
footprint FP-TFCR0603-MFG
pins: 1, 2

## CON1108
designator J?, comment value HDR-2.54 Male 1x2  Populated: DNP  Legend Note: THERMD  (hidden comment: Header 1x2)
Manufacturer 1: FCI; Manufacturer Part Number 1: 68000-202HLF; Manufacturer 10: Shanghai NS-TECH; Manufacturer Part Number 10: NS-201-SH0100-1*2; MCHP-ID: CON1108; Description_: CON HDR-2.54 Male 1x2 Gold 5.84MH TH VERT; Dev Tools Status: Production; Owner: Bogdan P (M91398); Restricted Sourcing: No
footprint HDR_M_2.54_1x2
pins: 1, 2
9 alternate drawings of the same symbol

## CON1734
designator J?, comment Legend Note: QSPI  (hidden comment: CON-10P-TC2050-SMT-NO-LEGS)
CON TAG 10P TC2050 SMT; Manufacturer 1: Tag-Connect LLC; Manufacturer Part Number 1: TC2050-IDC-NL; MCHP-ID: CON1734; Symbol: CON TAG 10P TC2050 SMT NO LEGS; Dev Tools Status: Design; Owner: Jesus Aviles; Populated: DNP; Restricted Sourcing: No
footprint CON_TAG TC2050 10P NO LEGS
pins: 1, 2, 3, 4, 5, 6, 7, 8, 9, 10

## CON1885
designator TP?, comment Legend Note: 2V5  (hidden comment: Test Point No BOM)  (no BOM)
Test Point; MCHP-ID: CON1885; Value: TP TH D1H0.6; Description_: CON TP PAD PCB TH D1H0.6; Dev Tools Status: Design; Owner: Gabor Bihari; Populated: DNP
footprint TP_1x0.6
pins: 1

## CON2256
designator J?, comment value FTSH-105-01-F-DV-007-K-P-TR  Legend Note: DEBUG  (hidden comment: Header 2x5 POS 7 POLARIZED)
Manufacturer 1: Samtec Inc.; MCHP-ID: CON2256; Description_: CON HDR-1.27 MALE 2x5 Missing Pin 7 Polarized SMD VERT; Dev Tools Status: Production; Owner: Manikandan Balakrishnan; Populated: YES; Current: 3.4A per Contact; Restricted Sourcing: No
footprint HDR_M_1.27_2x5_SMD_V_SAM_FTSH-105-01-F-DV-007-K
pins: 1, 2, 3, 4, 5, 6, 8, 9, 10
3 alternate drawings of the same symbol

## CON2551
designator J?, comment value MODULAR RJ45  Legend Note: MANAGEMENT  (hidden comment: CON_RJ-45_L829-1J1T-43)
Manufacturer 1: Bel Fuse; MCHP-ID: CON2551; Description_: CON MODULAR JACK RJ45 10/100/1000 MAGNETICS 2xLEDs SHIELD TH; Dev Tools Status: Design; Owner: Sam Charles; Populated: YES; Restricted Sourcing: No
footprint CON_JACK_RJ45_L829-1J1T-43
pins: 0 SHLD (power), 1, 2, 3, 4, 5, 6, 7, 8, 9, 10, 11, 12, 13, 14, 15, 16, 17

## CSD18540Q5B
designator Q?
-55℃~+175℃ 1 N-channel 1.9V 2.6mΩ 205A 20pF 3.8W 4.23nF 41nC@10V 60V 808pF N-Channel VSON-8(5x6) MOSFETs ROHS
footprint VSON-CLIP-8_L5.0-W6.0-P1.27-BL
pins: 1 S, 2 S, 3 S, 4 G, 5 D, 6 D, 7 D, 8 D

## DB910-7.62-2P
designator CN?, comment DB910-7.62-2P-GN-S
-40℃~+105℃ 0.5~4 1 10~26 1x2P 2 21.8mm 2P 300V 30A 7.62mm Green M3 Through Hole Plugin,P=7.62mm Screw Terminal Blocks ROHS
footprint CONN-TH_2P-P7.62_DB910-7.62-2P
pins: 1, 2

## DIODE1400
designator D?, comment value GREEN, YELLOW  Legend Note: GN= "RUN", YEL="RESET"  (hidden comment: LED_Dual_553-0123)
Manufacturer 1: Dialight; Manufacturer Part Number 1: 5530123F; MCHP-ID: DIODE1400; Description_: DIO LED BI GREEN, YELLOW 2.0V 10mA TH 553-0XXX; Dev Tools Status: Design; Type: LED Bicolor; Forward Current: 10mA; Owner: Sam Charles; Populated: YES; Restricted Sourcing: No
footprint DIO_LED_DUAL_553-0123
pins: 1, 2, 3, 4

## ESD5304D
designator U?
footprint DFN2510-10_L2.5-W1.0-P0.50-BL
pins: 1 I/O_1, 2 I/O_2, 3 GND, 4 I/O_3, 5 I/O_4, 6 NC, 7 NC, 8 GND, 9 NC, 10 NC

## ESD5341N
designator U?
footprint DFN1006-2L-RD
pins: 1, 2

## ESD5341N_1
designator U?, comment ESD5341N
footprint DFN1006-2L-RD
pins: 1, 2

## FB1007
designator FB?, comment value 33R  Saturation Current: 3A  (hidden comment: Ferrite Bead)
Manufacturer 1: Murata; Manufacturer Part Number 1: BLM18PG330SN1D; MCHP-ID: FB1007; Description_: FERRITE 33R@100MHz 3A SMD 0603; Dev Tools Status: Production; Owner: Ranjana Kumari; DCR: 0.025R; Test Frequency: 100MHz; Populated: YES; Restricted Sourcing: No
footprint IND_C_0603
pins: 1, 2
2 alternate drawings of the same symbol

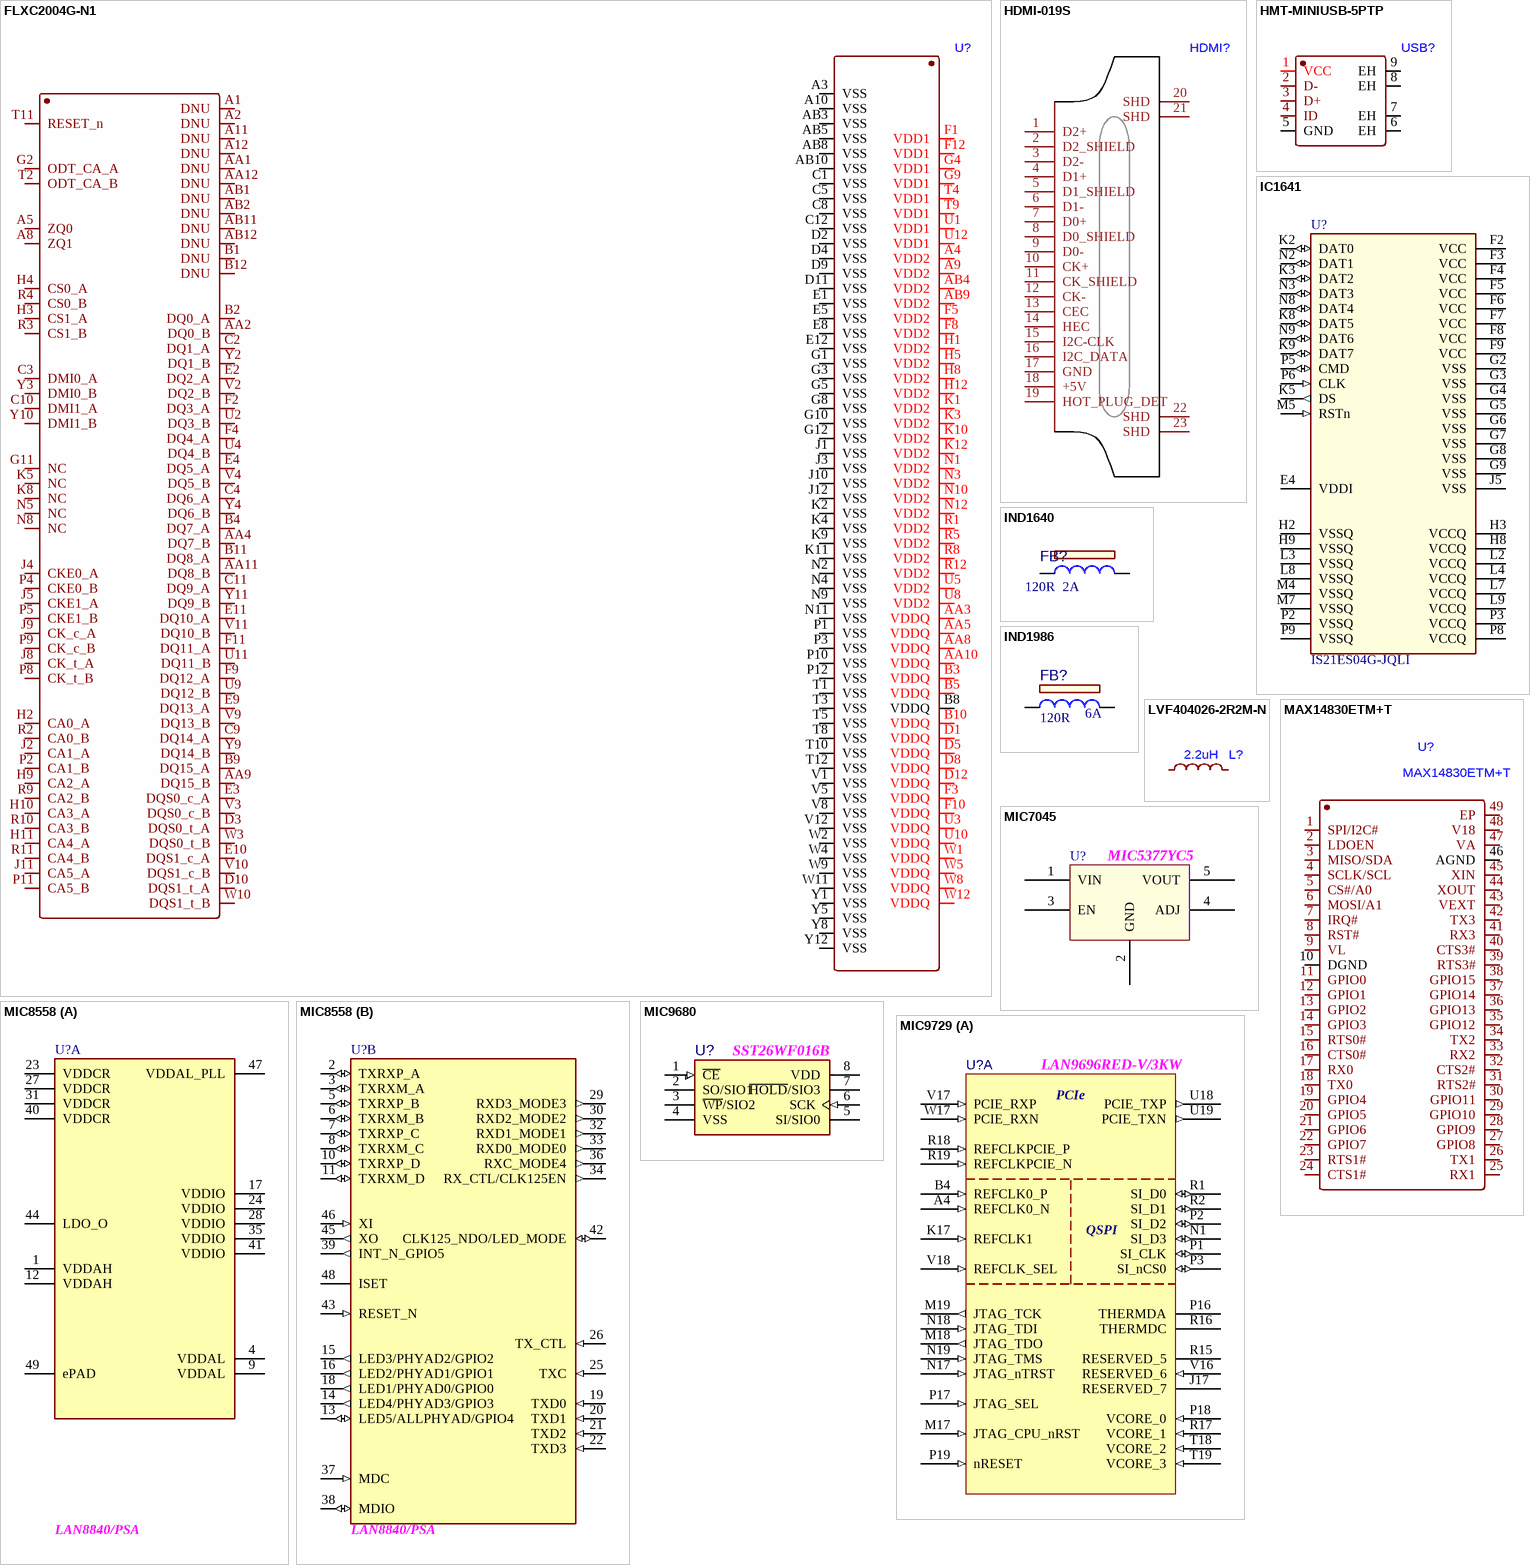
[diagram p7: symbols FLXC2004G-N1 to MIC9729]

## FLXC2004G-N1
designator U?
footprint WFBGA-200_L14.5-W10.0-BL_MT53D512M32D2DS
pins: A1 DNU, A2 DNU, A3 VSS, A4 VDD2, A5 ZQ0, A8 ZQ1, A9 VDD2, A10 VSS, A11 DNU, A12 DNU, AA1 DNU, AA2 DQ0_B, AA3 VDDQ, AA4 DQ7_B, AA5 VDDQ, AA8 VDDQ, AA9 DQ15_B, AA10 VDDQ, AA11 DQ8_B, AA12 DNU, AB1 DNU, AB2 DNU, AB3 VSS, AB4 VDD2, AB5 VSS, AB8 VSS, AB9 VDD2, AB10 VSS, AB11 DNU, AB12 DNU, B1 DNU, B2 DQ0_A, B3 VDDQ, B4 DQ7_A, B5 VDDQ, B8 VDDQ, B9 DQ15_A, B10 VDDQ, B11 DQ8_A, B12 DNU, C1 VSS, C2 DQ1_A, C3 DMI0_A, C4 DQ6_A, C5 VSS, C8 VSS, C9 DQ14_A, C10 DMI1_A, C11 DQ9_A, C12 VSS, D1 VDDQ, D2 VSS, D3 DQS0_t_A, D4 VSS, D5 VDDQ, D8 VDDQ, D9 VSS, D10 DQS1_t_A, D11 VSS, D12 VDDQ, E1 VSS, E2 DQ2_A, E3 DQS0_c_A, E4 DQ5_A, E5 VSS, E8 VSS, E9 DQ13_A, E10 DQS1_c_A, E11 DQ10_A, E12 VSS, F1 VDD1, F2 DQ3_A, F3 VDDQ, F4 DQ4_A, F5 VDD2, F8 VDD2, F9 DQ12_A, F10 VDDQ, F11 DQ11_A, F12 VDD1, G1 VSS, G2 ODT_CA_A, G3 VSS, G4 VDD1, G5 VSS, G8 VSS, G9 VDD1, G10 VSS, G11 NC, G12 VSS, H1 VDD2, H2 CA0_A, H3 CS1_A, H4 CS0_A, H5 VDD2, H8 VDD2, H9 CA2_A, H10 CA3_A, H11 CA4_A, H12 VDD2, J1 VSS, J2 CA1_A, J3 VSS, J4 CKE0_A, J5 CKE1_A, J8 CK_t_A, J9 CK_c_A, J10 VSS, J11 CA5_A, J12 VSS, K1 VDD2, K2 VSS, K3 VDD2, K4 VSS, K5 NC, K8 NC, K9 VSS, K10 VDD2, K11 VSS, K12 VDD2, N1 VDD2, N2 VSS, N3 VDD2, N4 VSS, N5 NC, N8 NC, N9 VSS, N10 VDD2, N11 VSS, N12 VDD2, P1 VSS, P2 CA1_B, P3 VSS, P4 CKE0_B, P5 CKE1_B, P8 CK_t_B, P9 CK_c_B, P10 VSS, P11 CA5_B, P12 VSS, R1 VDD2, R2 CA0_B, R3 CS1_B, R4 CS0_B, R5 VDD2, R8 VDD2, R9 CA2_B, R10 CA3_B, R11 CA4_B, R12 VDD2, T1 VSS, T2 ODT_CA_B, T3 VSS, T4 VDD1, T5 VSS, T8 VSS, T9 VDD1, T10 VSS, T11 RESET_n, T12 VSS, U1 VDD1, U2 DQ3_B, U3 VDDQ, U4 DQ4_B, U5 VDD2, U8 VDD2, U9 DQ12_B, U10 VDDQ, U11 DQ11_B, U12 VDD1, V1 VSS, V2 DQ2_B, V3 DQS0_c_B, V4 DQ5_B, V5 VSS, V8 VSS, V9 DQ13_B, V10 DQS1_c_B, V11 DQ10_B, V12 VSS, W1 VDDQ, W2 VSS, W3 DQS0_t_B, W4 VSS, W5 VDDQ, W8 VDDQ, W9 VSS, W10 DQS1_t_B, W11 VSS, W12 VDDQ, Y1 VSS, Y2 DQ1_B, Y3 DMI0_B, Y4 DQ6_B, Y5 VSS, Y8 VSS, Y9 DQ14_B, Y10 DMI1_B, Y11 DQ9_B, Y12 VSS

## HDMI-019S
designator HDMI?
footprint HDMI-SMD_HDMI-019S
pins: 1 D2+, 2 D2_SHIELD, 3 D2-, 4 D1+, 5 D1_SHIELD, 6 D1-, 7 D0+, 8 D0_SHIELD, 9 D0-, 10 CK+, 11 CK_SHIELD, 12 CK-, 13 CEC, 14 HEC, 15 I2C-CLK, 16 I2C_DATA, 17 GND, 18 +5V, 19 HOT_PLUG_DET, 20 SHD, 21 SHD, 22 SHD, 23 SHD

## HMT-MINIUSB-5PTP
designator USB?
footprint MINI-USB-SMD_XY-5PTP-MINIUSB
pins: 1 VCC, 2 D-, 3 D+, 4 ID, 5 GND, 6 EH, 7 EH, 8 EH, 9 EH

## IC1641
designator U?, comment value IS21ES04G-JQLI  (hidden comment: eMMC MLC NAND flash 200MHz)
Manufacturer 1: Flexxon; Manufacturer Part Number 1: FEMC004GTTE7-T13-17; MCHP-ID: IC1641; Symbol: IS21ES04G-JQLI FBGA-100; Description_: IC MEMORY IS21ES04G 32Gb eMMC FBGA-100; Dev Tools Status: Production; Vin: 3.3V; Owner: Ilie Galan; Populated: YES; Restricted Sourcing: No
footprint FBGA-100_14x18
pins: E4 VDDI (power), F2 VCC (power), F3 VCC (power), F4 VCC (power), F5 VCC (power), F6 VCC (power), F7 VCC (power), F8 VCC (power), F9 VCC (power), G2 VSS (power), G3 VSS (power), G4 VSS (power), G5 VSS (power), G6 VSS (power), G7 VSS (power), G8 VSS (power), G9 VSS (power), H2 VSSQ (power), H3 VCCQ (power), H8 VCCQ (power), H9 VSSQ (power), J5 VSS (power), K2 DAT0 (io), K3 DAT2 (io), K5 DS (out), K8 DAT5 (io), K9 DAT7 (io), L2 VCCQ (power), L3 VSSQ (power), L4 VCCQ (power), L7 VCCQ (power), L8 VSSQ (power), L9 VCCQ (power), M4 VSSQ (power), M5 RSTn (in), M7 VSSQ (power), N2 DAT1 (io), N3 DAT3 (io), N8 DAT4 (io), N9 DAT6 (io), P2 VSSQ (power), P3 VCCQ (power), P5 CMD (io), P6 CLK (in), P8 VCCQ (power), P9 VSSQ (power)

## IND1640
designator FB?, comment value 120R  RMS Current: 2A  (hidden comment: Ferrite Bead)
Manufacturer 1: TDK Corporation; Manufacturer Part Number 1: MPZ1608S121ATDH5; MCHP-ID: IND1640; Description_: FERRITE 120R@100MHZ 2A SMD 0603; Dev Tools Status: Production; Owner: Sam Charles; DCR: 0.045R; Test Frequency: 100MHz; Populated: YES; Restricted Sourcing: No
footprint IND_C_0603
pins: 1, 2
2 alternate drawings of the same symbol

## IND1986
designator FB?, comment value 120R  Saturation Current: 6A  (hidden comment: Ferrite Bead)
Manufacturer 1: Murata; Manufacturer Part Number 1: BLM31KN121SZ1L; MCHP-ID: IND1986; Description_: FERRITE 120R@100MHz 6A 9mOhm SMD 1206 AEC-Q200; Dev Tools Status: Design; Owner: Mihai Chivu; DCR: 0.009R; Test Frequency: 100MHz; Populated: YES; Restricted Sourcing: No
footprint IND_C_1206
pins: 1, 2
2 alternate drawings of the same symbol

## LVF404026-2R2M-N
designator L?, comment 2.2uH
footprint IND-SMD_L4.0-W4.0
pins: 1, 2

## MAX14830ETM+T
designator U?
-40℃~+85℃ 1.71V~3.6V、1.71V~3.6V、2.35V~3.6V 128Byte 12Mbps 4 I2C、SPI、IrDA、RS-485、RS-232 With automatic flow control、Configurable GPIO、Auto Transceiver Direction Control、Interrupt Trigger TQFN-48-EP(7x7) UART ROHS
footprint TQFN-48_L7.0-W7.0-P0.50-BL-EP5.5
pins: 1 SPI/I2C#, 2 LDOEN, 3 MISO/SDA, 4 SCLK/SCL, 5 CS#/A0, 6 MOSI/A1, 7 IRQ#, 8 RST#, 9 VL, 10 DGND, 11 GPIO0, 12 GPIO1, 13 GPIO2, 14 GPIO3, 15 RTS0#, 16 CTS0#, 17 RX0, 18 TX0, 19 GPIO4, 20 GPIO5, 21 GPIO6, 22 GPIO7, 23 RTS1#, 24 CTS1#, 25 RX1, 26 TX1, 27 GPIO8, 28 GPIO9, 29 GPIO10, 30 GPIO11, 31 RTS2#, 32 CTS2#, 33 RX2, 34 TX2, 35 GPIO12, 36 GPIO13, 37 GPIO14, 38 GPIO15, 39 RTS3#, 40 CTS3#, 41 RX3, 42 TX3, 43 VEXT, 44 XOUT, 45 XIN, 46 AGND, 47 VA, 48 V18, 49 EP

## MIC7045
designator U?, comment MIC5377YC5
Manufacturer 1: Microchip Technology; Manufacturer Part Number 1: MIC5377YC5-TR; MCHP-ID: MIC7045; Description_: MCHP ANALOG LDO 5.3V MIC5377YC5-TR SC70-5; Dev Tools Status: Production; Owner: Tim Moffat; Populated: YES
footprint SC-70-5
pins: 1 VIN, 2 GND, 3 EN, 4 ADJ, 5 VOUT

## MIC8558
designator U?, comment Manufacturer Part Number 1: LAN8840/PSA  (hidden comment: LAN8840_QFN-48_TEST)
Manufacturer 1: Microchip Technology; MCHP-ID: MIC8558; Description_: MCHP INTERFACE ETHERNET LAN8840 QFN-48; Dev Tools Status: Design; Owner: Sam Charles; Populated: YES; Restricted Sourcing: No
footprint QFN-48_7x7_EP5.1x5.1
footprint QFN-48_7X7_SKT_HSIO
part A pins: 1 VDDAH (power), 4 VDDAL (power), 9 VDDAL (power), 12 VDDAH (power), 17 VDDIO (power), 23 VDDCR (power), 24 VDDIO (power), 27 VDDCR (power), 28 VDDIO (power), 31 VDDCR (power), 35 VDDIO (power), 40 VDDCR (power), 41 VDDIO (power), 44 LDO_O (power), 47 VDDAL_PLL (power), 49 ePAD (power)
part B pins: 2 TXRXP_A (io), 3 TXRXM_A (io), 5 TXRXP_B (io), 6 TXRXM_B (io), 7 TXRXP_C (io), 8 TXRXM_C (io), 10 TXRXP_D (io), 11 TXRXM_D (io), 13 LED5/ALLPHYAD/GPIO4 (io), 14 LED4/PHYAD3/GPIO3 (out), 15 LED3/PHYAD2/GPIO2 (out), 16 LED2/PHYAD1/GPIO1 (out), 18 LED1/PHYAD0/GPIO0 (out), 19 TXD0 (in), 20 TXD1 (in), 21 TXD2 (in), 22 TXD3 (in), 25 TXC (in), 26 TX_CTL (in), 29 RXD3_MODE3 (out), 30 RXD2_MODE2 (out), 32 RXD1_MODE1 (out), 33 RXD0_MODE0 (out), 34 RX_CTL/CLK125EN (out), 36 RXC_MODE4 (out), 37 MDC (in), 38 MDIO (io), 39 INT_N_GPIO5 (out), 42 CLK125_NDO/LED_MODE (io), 43 RESET_N (in), 45 XO (out), 46 XI (in), 48 ISET
1 alternate drawing of the same symbol

## MIC9680
designator U?, comment Legend Note: SST26WF016B  (hidden comment: SST26WFXXX SOIC-8)
Manufacturer 1: Microchip Technology; Manufacturer Part Number 1: SST26WF016BT-104I/SN; MCHP-ID: MIC9680; Value: SST26WF016; Description_: MCHP MEMORY SERIAL FLASH 16M 104MHz SST26WF016 SOIC-8; Dev Tools Status: Design; Owner: Sam Charles; Populated: YES; Restricted Sourcing: No
footprint SOIC-8
pins: 1 ~{CE} (in) "GND", 2 SO/SIO1 "GND", 3 ~{WP}/SIO2 "GND", 4 VSS (power) "GND", 5 SI/SIO0 "GND", 6 SCK (in) "GND", 7 ~{HOLD}/SIO3 "GND", 8 VDD (power) "GND"
3 alternate drawings of the same symbol

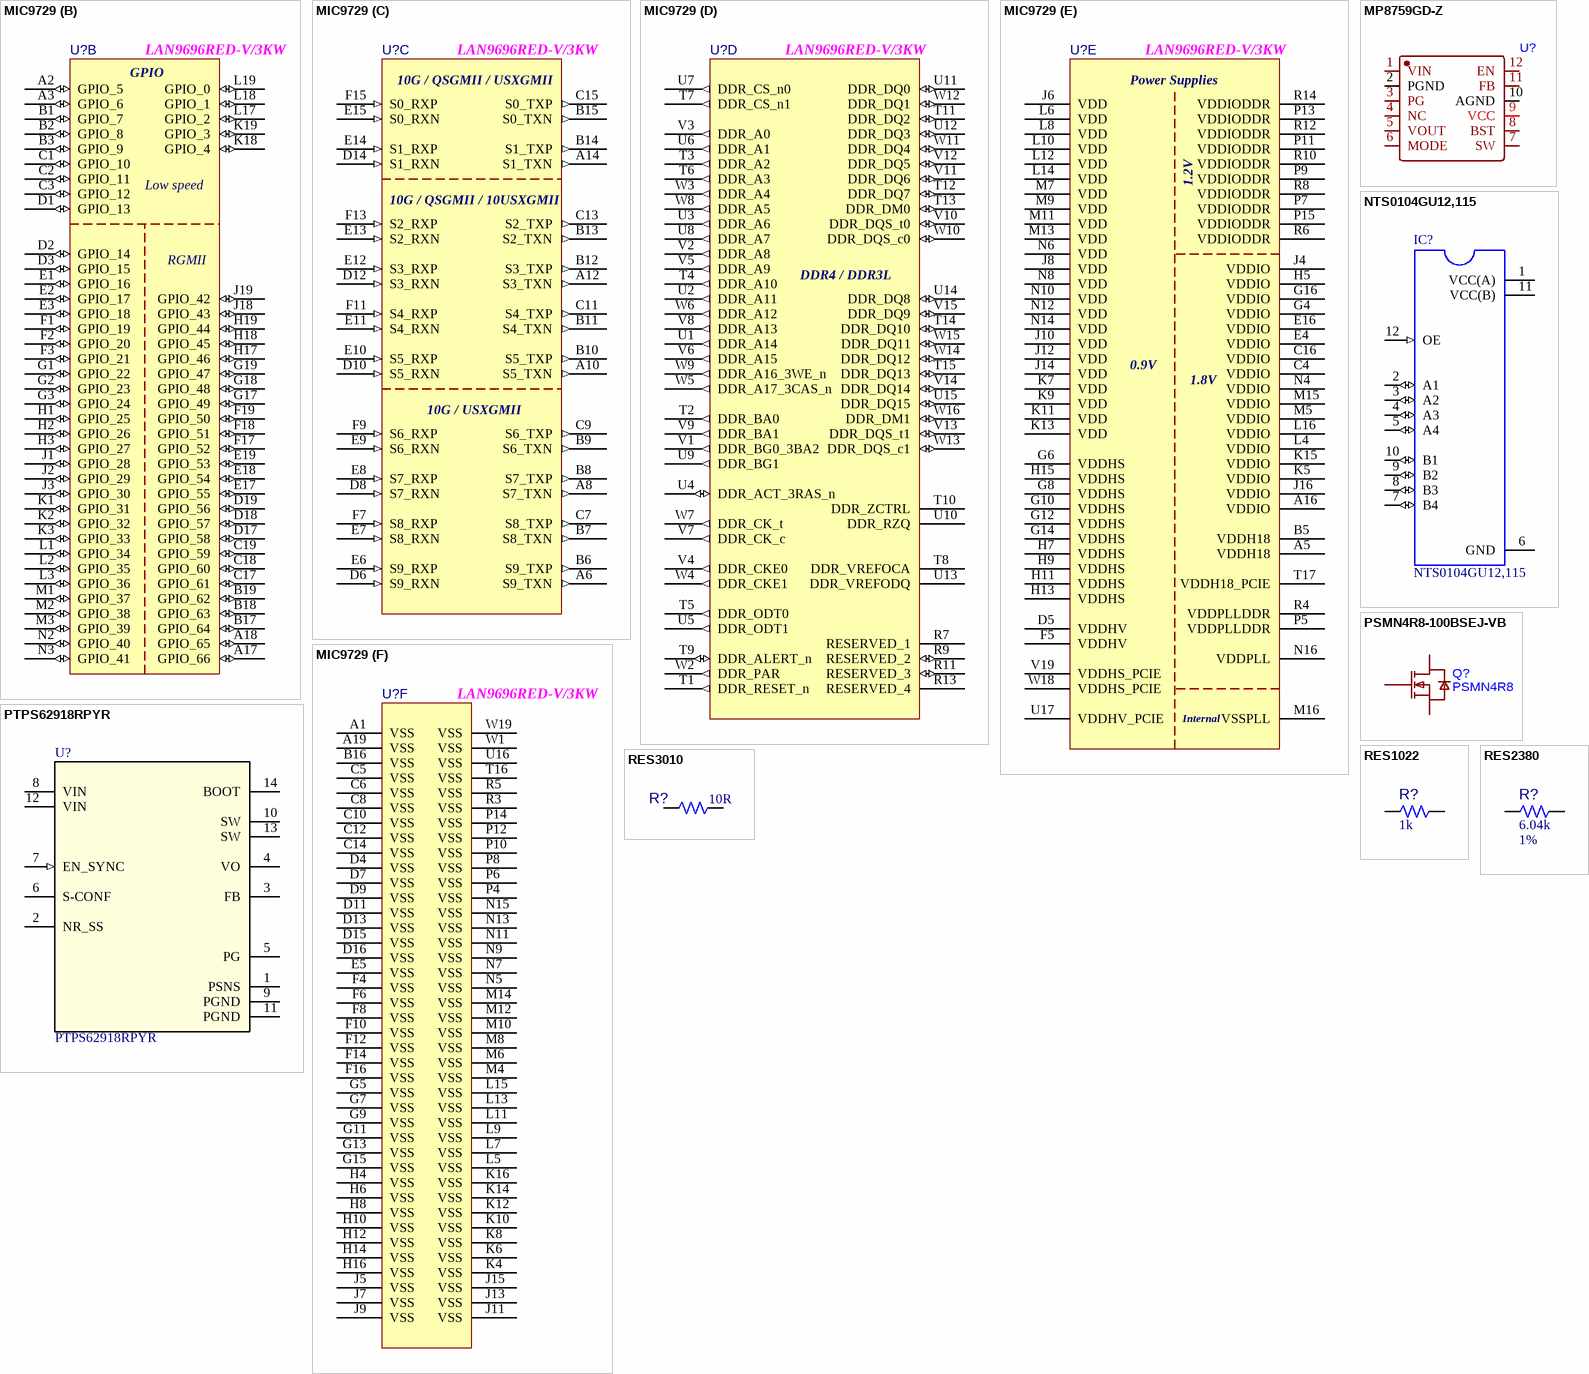
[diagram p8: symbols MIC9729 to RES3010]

## MIC9729
designator U?, comment LAN9696RED-V/3KW
Manufacturer 1: Microchip Technology; MCHP-ID: MIC9729; Description_: MCHP INTERFACE Industrial ETH SWITCH LAN9694 BGA356; Symbol: LAN969X BGA-356; Dev Tools Status: Design; Owner: Manikandan Balakrishnan; Populated: YES; Restricted Sourcing: No
footprint BGA-356_P0.8_17x17x1.68
footprint BGA-356_P0.8_17x17x1.3_SOCKET_Winway71161970 (Footprint not found)
part A pins: A4 REFCLK0_N (in), B4 REFCLK0_P (in), J17 RESERVED_7, K17 REFCLK1 (in), M17 JTAG_CPU_nRST (in), M18 JTAG_TDO (out), M19 JTAG_TCK (out), N1 SI_D3 (io), N17 JTAG_nTRST (in), N18 JTAG_TDI (in), N19 JTAG_TMS (in), P1 SI_CLK (io), P2 SI_D2 (io), P3 SI_nCS0 (io), P16 THERMDA, P17 JTAG_SEL (in), P18 VCORE_0 (in), P19 nRESET (in), R1 SI_D0 (io), R2 SI_D1 (io), R15 RESERVED_5 (power), R16 THERMDC, R17 VCORE_1 (in), R18 REFCLKPCIE_P (in), R19 REFCLKPCIE_N (in), T18 VCORE_2 (in), T19 VCORE_3 (in), U18 PCIE_TXP (out), U19 PCIE_TXN (out), V16 RESERVED_6 (in), V17 PCIE_RXP (in), V18 REFCLK_SEL (in), W17 PCIE_RXN (in)
part B pins: A2 GPIO_5 (io), A3 GPIO_6 (io), A17 GPIO_66 (io), A18 GPIO_65 (io), B1 GPIO_7 (io), B2 GPIO_8 (io), B3 GPIO_9 (io), B17 GPIO_64 (io), B18 GPIO_63 (io), B19 GPIO_62 (io), C1 GPIO_10 (io), C2 GPIO_11 (io), C3 GPIO_12 (io), C17 GPIO_61 (io), C18 GPIO_60 (io), C19 GPIO_59 (io), D1 GPIO_13 (io), D2 GPIO_14 (io), D3 GPIO_15 (io), D17 GPIO_58 (io), D18 GPIO_57 (io), D19 GPIO_56 (io), E1 GPIO_16 (io), E2 GPIO_17 (io), E3 GPIO_18 (io), E17 GPIO_55 (io), E18 GPIO_54 (io), E19 GPIO_53 (io), F1 GPIO_19 (io), F2 GPIO_20 (io), F3 GPIO_21 (io), F17 GPIO_52 (io), F18 GPIO_51 (io), F19 GPIO_50 (io), G1 GPIO_22 (io), G2 GPIO_23 (io), G3 GPIO_24 (io), G17 GPIO_49 (io), G18 GPIO_48 (io), G19 GPIO_47 (io), H1 GPIO_25 (io), H2 GPIO_26 (io), H3 GPIO_27 (io), H17 GPIO_46 (io), H18 GPIO_45 (io), H19 GPIO_44 (io), J1 GPIO_28 (io), J2 GPIO_29 (io), J3 GPIO_30 (io), J18 GPIO_43 (io), J19 GPIO_42 (io), K1 GPIO_31 (io), K2 GPIO_32 (io), K3 GPIO_33 (io), K18 GPIO_4 (io), K19 GPIO_3 (io), L1 GPIO_34 (io), L2 GPIO_35 (io), L3 GPIO_36 (io), L17 GPIO_2 (io), L18 GPIO_1 (io), L19 GPIO_0 (io), M1 GPIO_37 (io), M2 GPIO_38 (io), M3 GPIO_39 (io), N2 GPIO_40 (io), N3 GPIO_41 (io)
part C pins: A6 S9_TXN (out), A8 S7_TXN (out), A10 S5_TXN (out), A12 S3_TXN (out), A14 S1_TXN (out), B6 S9_TXP (out), B7 S8_TXN (out), B8 S7_TXP (out), B9 S6_TXN (out), B10 S5_TXP (out), B11 S4_TXN (out), B12 S3_TXP (out), B13 S2_TXN (out), B14 S1_TXP (out), B15 S0_TXN (out), C7 S8_TXP (out), C9 S6_TXP (out), C11 S4_TXP (out), C13 S2_TXP (out), C15 S0_TXP (out), D6 S9_RXN (in), D8 S7_RXN (in), D10 S5_RXN (in), D12 S3_RXN (in), D14 S1_RXN (in), E6 S9_RXP (in), E7 S8_RXN (in), E8 S7_RXP (in), E9 S6_RXN (in), E10 S5_RXP (in), E11 S4_RXN (in), E12 S3_RXP (in), E13 S2_RXN (in), E14 S1_RXP (in), E15 S0_RXN (in), F7 S8_RXP (in), F9 S6_RXP (in), F11 S4_RXP (in), F13 S2_RXP (in), F15 S0_RXP (in)
part D pins: R7 RESERVED_1, R9 RESERVED_2 (io), R11 RESERVED_3 (io), R13 RESERVED_4, T1 DDR_RESET_n (out), T2 DDR_BA0 (out), T3 DDR_A2 (out), T4 DDR_A10 (out), T5 DDR_ODT0 (out), T6 DDR_A3 (out), T7 DDR_CS_n1 (out), T8 DDR_VREFOCA, T9 DDR_ALERT_n (io), T10 DDR_ZCTRL, T11 DDR_DQ2 (io), T12 DDR_DQ7 (io), T13 DDR_DM0 (io), T14 DDR_DQ10 (io), T15 DDR_DQ13 (io), U1 DDR_A14 (out), U2 DDR_A11 (out), U3 DDR_A6 (out), U4 DDR_ACT_3RAS_n (io), U5 DDR_ODT1 (out), U6 DDR_A1 (out), U7 DDR_CS_n0 (out), U8 DDR_A7 (out), U9 DDR_BG1 (out), U10 DDR_RZQ, U11 DDR_DQ0 (io), U12 DDR_DQ3 (io), U13 DDR_VREFODQ, U14 DDR_DQ8 (io), U15 DDR_DQ15 (io), V1 DDR_BG0_3BA2 (out), V2 DDR_A8 (out), V3 DDR_A0 (out), V4 DDR_CKE0 (out), V5 DDR_A9 (out), V6 DDR_A15 (out), V7 DDR_CK_c (out), V8 DDR_A13 (out), V9 DDR_BA1 (out), V10 DDR_DQS_t0 (io), V11 DDR_DQ6 (io), V12 DDR_DQ5 (io), V13 DDR_DQS_t1 (io), V14 DDR_DQ14 (io), V15 DDR_DQ9 (io), W2 DDR_PAR (out), W3 DDR_A4 (out), W4 DDR_CKE1 (out), W5 DDR_A17_3CAS_n (out), W6 DDR_A12 (out), W7 DDR_CK_t (out), W8 DDR_A5 (out), W9 DDR_A16_3WE_n (out), W10 DDR_DQS_c0 (io), W11 DDR_DQ4 (io), W12 DDR_DQ1 (io), W13 DDR_DQS_c1 (io), W14 DDR_DQ12 (io), W15 DDR_DQ11 (io), W16 DDR_DM1 (io)
part E pins: A5 VDDH18 (power), A16 VDDIO (power), B5 VDDH18 (power), C4 VDDIO (power), C16 VDDIO (power), D5 VDDHV (power), E4 VDDIO (power), E16 VDDIO (power), F5 VDDHV (power), G4 VDDIO (power), G6 VDDHS (power), G8 VDDHS (power), G10 VDDHS (power), G12 VDDHS (power), G14 VDDHS (power), G16 VDDIO (power), H5 VDDIO (power), H7 VDDHS (power), H9 VDDHS (power), H11 VDDHS (power), H13 VDDHS (power), H15 VDDHS (power), J4 VDDIO (power), J6 VDD (power), J8 VDD (power), J10 VDD (power), J12 VDD (power), J14 VDD (power), J16 VDDIO (power), K5 VDDIO (power), K7 VDD (power), K9 VDD (power), K11 VDD (power), K13 VDD (power), K15 VDDIO (power), L4 VDDIO (power), L6 VDD (power), L8 VDD (power), L10 VDD (power), L12 VDD (power), L14 VDD (power), L16 VDDIO (power), M5 VDDIO (power), M7 VDD (power), M9 VDD (power), M11 VDD (power), M13 VDD (power), M15 VDDIO (power), M16 VSSPLL (power), N4 VDDIO (power), N6 VDD (power), N8 VDD (power), N10 VDD (power), N12 VDD (power), N14 VDD (power), N16 VDDPLL (power), P5 VDDPLLDDR (power), P7 VDDIODDR (power), P9 VDDIODDR (power), P11 VDDIODDR (power), P13 VDDIODDR (power), P15 VDDIODDR (power), R4 VDDPLLDDR (power), R6 VDDIODDR (power), R8 VDDIODDR (power), R10 VDDIODDR (power), R12 VDDIODDR (power), R14 VDDIODDR (power), T17 VDDH18_PCIE (power), U17 VDDHV_PCIE (power), V19 VDDHS_PCIE (power), W18 VDDHS_PCIE (power)
part F pins: A1 VSS (power), A19 VSS (power), B16 VSS (power), C5 VSS (power), C6 VSS (power), C8 VSS (power), C10 VSS (power), C12 VSS (power), C14 VSS (power), D4 VSS (power), D7 VSS (power), D9 VSS (power), D11 VSS (power), D13 VSS (power), D15 VSS (power), D16 VSS (power), E5 VSS (power), F4 VSS (power), F6 VSS (power), F8 VSS (power), F10 VSS (power), F12 VSS (power), F14 VSS (power), F16 VSS (power), G5 VSS (power), G7 VSS (power), G9 VSS (power), G11 VSS (power), G13 VSS (power), G15 VSS (power), H4 VSS (power), H6 VSS (power), H8 VSS (power), H10 VSS (power), H12 VSS (power), H14 VSS (power), H16 VSS (power), J5 VSS (power), J7 VSS (power), J9 VSS (power), J11 VSS (power), J13 VSS (power), J15 VSS (power), K4 VSS (power), K6 VSS (power), K8 VSS (power), K10 VSS (power), K12 VSS (power), K14 VSS (power), K16 VSS (power), L5 VSS (power), L7 VSS (power), L9 VSS (power), L11 VSS (power), L13 VSS (power), L15 VSS (power), M4 VSS (power), M6 VSS (power), M8 VSS (power), M10 VSS (power), M12 VSS (power), M14 VSS (power), N5 VSS (power), N7 VSS (power), N9 VSS (power), N11 VSS (power), N13 VSS (power), N15 VSS (power), P4 VSS (power), P6 VSS (power), P8 VSS (power), P10 VSS (power), P12 VSS (power), P14 VSS (power), R3 VSS (power), R5 VSS (power), T16 VSS (power), U16 VSS (power), W1 VSS (power), W19 VSS (power)

## MP8759GD-Z
designator U?
footprint QFN-12_L3.0-W2.0-P0.5-TL_NB680
pins: 1 VIN, 2 PGND, 3 PG, 4 NC, 5 VOUT, 6 MODE, 7 SW, 8 BST, 9 VCC, 10 AGND, 11 FB, 12 EN

## NTS0104GU12,115
designator IC?
Voltage Level Translator Bidirectional 1 Circuit 4 Channel 50Mbps 12-XQFN _2x1.7_; MF: NXP USA
footprint QFN40P170X200X50-12N
pins: 1 VCC(A) (power), 2 A1 (io), 3 A2 (io), 4 A3 (io), 5 A4 (io), 6 GND, 7 B4 (io), 8 B3 (io), 9 B2 (io), 10 B1 (io), 11 VCC(B) (power), 12 OE (in)

## PSMN4R8-100BSEJ-VB
designator Q?, comment PSMN4R8
PSMN4R8-100BSEJ-VB
footprint TO-263-2_L10.2-W8.5-P2.54-LS15.2-TL
pins: 1 G, 2 D, 3 S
